(* Logix 5000 project; controller MyControlLogix 1756-L63 rev 15.1; software revision 15.02 *)
// Sample ladder logic for MVI56-AFC module

TASK MainTask (continuous, watchdog 500 ms) : MainProgram

MODULES
   Local : 1756-L63 (ICP 0, rev 15.1)
      AFC : vendor 1 type 0 code 15 (ICP 1, rev 1.1, Output RPI 5 ms)
END_MODULES

TYPE AFC :   // Main user defined data type
STRUCT
   Meters : AFC_Meters[16];   // Stores meter process variables, results, analysis (gas) and module profile
   MeterSignals : AFC_Meter_Reset;   // Sets meter signals (write archive, reset accumulator and select stream)
   ModbusGateway : AFC_Modbus;   // Reads and write data between processor and module modbus table
   ModbusMaster : AFC_ModbusMaster;   // Setup modbus master commands to be sent to remote slaves (through Port 3)
   ModbusPassThru : AFC_ModbusPassThru;   // Modbus pass-thru data
   Prove : AFC_Prove;   // Proving implementation (only firmware 2.07.000 or later)
   Flags : AFC_Flag;   // Wallclock update commands
   EnableMeter : AFC_Meter;   // Enable meters (this action can also be performed through AFC Manager)
   DisableMeter : AFC_Meter;   // Disable meters (this action can also be performed through AFC Manager)
   EnableStatus : AFC_Meter;   // Meter current status (0=disabled, 1=enabled)
   Site_Status : AFC_Site_Status;   // Site status
   Site_Alarms : AFC_Site_Alarms;   // Site Alarms
   CycleCounter : INT;   // Reflects current block ID calculated by ladder to be sent to the module
   inputbuffer : INT[250];   // Input buffer contains the complete block to be copied from the module
   outputbuffer : INT[248];   // Output buffer contains data the complete block to be copied to the module
   clockstructure : AFC_Time;   // Stores clock information
   Util : AFC_Util;   // Convenience variables used by ladder logic
END_STRUCT
END_TYPE

TYPE AFC_Analysis_High :   // High precision (floating point) Gas Analysis support. This feature is only supported for firmware version 2.07.000 or later
STRUCT
   EnableOnce : BOOL;   // Set to ON to request the high precision analysis update one time. It automatically resets to 0 after the request.
   Stream : INT;   // Stream number. Range is 0 (active) and 1 to 4.
   Components : AFC_Components_High;   // AFC High Precision Molar Analysis (floating point)
END_STRUCT
END_TYPE

TYPE AFC_Analysis_Low :   // Low precision (16-bit word) Gas Analysis support.
STRUCT
   EnableContinuous : BOOL;   // Set to ON to update the low precision molar analysis. The data will be updated continuously while the molar analysis is updated.
   Stream : INT;   // Select stream for molar analysis (low precision) update. Valid range is 0 (active) and 1 to 4.
   Components : AFC_Components_Low;   // Gas components in low precision format (16-bit word)
END_STRUCT
END_TYPE

TYPE AFC_Analysis_Status :   // Contains stream configuration information concerning high/low precision.
STRUCT
   Update : BOOL;   // Trigger update of analysis status
   Stream_Precision : SINT[4];   // Stream Precision ( 1 = Low, 2 = High)
   Slot_In_Stream : SINT[4];   // Slot number associated to each stream (0-BASED) Ex: (Slot_In_Stream[0] = 1 means stream 1 is set for slot 2)
   Slot_Precision : SINT[4];   // Precision of each slot (0-BASED) (2=high precision/first slot, 1=low precision,0=high precision/second slot)
END_STRUCT
END_TYPE

TYPE AFC_Components_High :   // High precision gas component analysis (only supported version 2.07.000)
STRUCT
   C1 : REAL;   // Methane
   N2 : REAL;   // Nitrogen
   CO2 : REAL;   // Carbon Dioxide
   C2 : REAL;   // Ethane
   C3 : REAL;   // Propane
   H20 : REAL;   // Water
   H2S : REAL;   // Hydrogen Sulphide
   H2 : REAL;   // Hydrogen
   CO : REAL;   // Carbon Monoxide
   O2 : REAL;   // Oxygen
   IC4 : REAL;   // Iso-butane
   NC4 : REAL;   // Normal Butane
   IC5 : REAL;   // Iso-pentane
   NC5 : REAL;   // Normal-pentane
   C6 : REAL;   // Hexane
   C7 : REAL;   // Heptane
   C8 : REAL;   // Octane
   C9 : REAL;   // Nonane
   C10 : REAL;   // Decane
   He : REAL;   // Helium
   Ar : REAL;   // Argon
   NeoC5 : REAL;   // Not Used
   Ux_User1 : REAL;   // Not Used
   Uy_User2 : REAL;   // Not Used
END_STRUCT
END_TYPE

TYPE AFC_Components_Low :   // Low precision gas component analysis
STRUCT
   C1 : INT;   // Methane
   N2 : INT;   // Nitrogen
   CO2 : INT;   // Carbon dioxide
   C2 : INT;   // Ethane
   C3 : INT;   // Propane
   H20 : INT;   // Water
   H2S : INT;   // Hydrogen sulphide
   H2 : INT;   // Hydrogen
   CO : INT;   // Carbon monoxide
   O2 : INT;   // Oxygen
   IC4 : INT;   // Iso-butane
   NC4 : INT;   // Normal butane
   IC5 : INT;   // Iso-pentane
   NC5 : INT;   // Normal pentane
   C6 : INT;   // Hexane
   C7 : INT;   // Heptane
   C8 : INT;   // Octane
   C9 : INT;   // Nonane
   C10 : INT;   // Decane
   He : INT;   // Helium
   Ar : INT;   // Argon
   NeoC5 : INT;   // Not used
   Ux_User1 : INT;   // Not used
   Uy_User2 : INT;   // Not used
END_STRUCT
END_TYPE

TYPE AFC_Flag :   // Flags contains status information updated by ladder and also trigger bits for clock update
STRUCT
   AFC_Stopped : BOOL;   // Indicates that the module has sent a new input block to be processed by ladder - UPDATED BY LADDER
   AFC_InputSequenceNum : INT;   // Meter number (0 -15) associated to blocks 1-16. Used to update "Profile" (meter type and product group.) UPDATED BY LADDER
   AFC_Set_Clock : BOOL;   // Set to 1 to update module wallclock (using processor as a source) UPDATED BY USER
   plc_set_clock : BOOL;   // Set to 1 to set processor wallclock UPDATED BY USER
END_STRUCT
END_TYPE

TYPE AFC_Meter :   // Used for meter enable and disable tags
STRUCT
   Meter1 : BOOL;   // Meter 1
   Meter2 : BOOL;   // Meter 2
   Meter3 : BOOL;   // Meter 3
   Meter4 : BOOL;   // Meter 4
   Meter5 : BOOL;   // Meter 5
   Meter6 : BOOL;   // Meter 6
   Meter7 : BOOL;   // Meter 7
   Meter8 : BOOL;   // Meter 8
   Meter9 : BOOL;   // Meter 9
   Meter10 : BOOL;   // Meter 10
   Meter11 : BOOL;   // Meter 11
   Meter12 : BOOL;   // Meter 12
   Meter13 : BOOL;   // Meter 13
   Meter14 : BOOL;   // Meter 14
   Meter15 : BOOL;   // Meter 15
   Meter16 : BOOL;   // Meter 16
END_STRUCT
END_TYPE

TYPE AFC_Meter_Analysis :   // Meter analysis components. Allows the processor to update molar analysis for low precision and high precision streams.
STRUCT
   Low_Precision : AFC_Analysis_Low;   // Low precision gas components (16-bit word per component)
   High_Precision : AFC_Analysis_High;   // High precision gas components (floating point per component). Only supported for firmware version 2.07.000 or later
   Status : AFC_Analysis_Status;   // Stream analysis status - contains stream and slot configuration data
END_STRUCT
END_TYPE

TYPE AFC_Meter_Differential_Gas_Input :   // Calculation results for differential meter with gas product
STRUCT
   Net_Accumulator : DINT;   // Net accumulator
   Net_Flowrate : REAL;   // Net flow rate
   Gross_Flowrate : REAL;   // Gross flow rate
   Fpv : REAL;   // Super compressibility
   Cprime : REAL;   // Cprime
END_STRUCT
END_TYPE

TYPE AFC_Meter_Differential_Gas_Output :   // Process Variables for differential meter with gas product
STRUCT
   Temperature : REAL;   // Temperature
   Pressure : REAL;   // Static pressure
   Differential_Pressure : REAL;   // Differential pressure if Primary Input = Differential pressure OR Flow Rate if Primary Input = Flow rate
END_STRUCT
END_TYPE

TYPE AFC_Meter_Differential_Liquid_Input :   // Calculation Results for differential meter with lliquid product
STRUCT
   Net_Accumulator : DINT;   // Net accumulator
   Net_Flowrate : REAL;   // Net flow rate
   Gross_Accumulator : DINT;   // Gross acumulator
   Gross_Standard_Accumulator : DINT;   // Gross standard accumulator
   Mass_Accumulator : DINT;   // Mass accumulator
END_STRUCT
END_TYPE

TYPE AFC_Meter_Differential_Liquid_Output :   // Process Variables for differential meter with liquid product
STRUCT
   Water_Percent : INT;   // Water %
   Temperature : REAL;   // Temperature
   Pressure : REAL;   // Static Pressure
   Differential_Pressure : REAL;   // Differential pressure if Primary Input = Differential pressure OR Flow Rate if Primary Input = Flow rate
   Density : REAL;   // Density
END_STRUCT
END_TYPE

TYPE AFC_Meter_Linear_Gas_Input :   // Calculation Results for linear meter with gas product
STRUCT
   Net_Accumulator : DINT;   // Net accumulator
   Net_Flowrate : REAL;   // Net flow rate
   Gross_Flowrate : REAL;   // Gross flow rate
   Fpv : REAL;   // Supercompressibility
   CPrime : REAL;   // CPrime
END_STRUCT
END_TYPE

TYPE AFC_Meter_Linear_Gas_Output :   // Process Variables for linear meter with gas product
STRUCT
   Temperature : REAL;   // Temperature
   Pressure : REAL;   // Pressure
   Meter_Pulses : DINT;   // Pulse count
   Pulse_Frequency : REAL;   // Pulse Frequency (Hz)
END_STRUCT
END_TYPE

TYPE AFC_Meter_Linear_Liquid_Input :   // Calculation Results for linear meter with liquid product
STRUCT
   Net_Accumulator : DINT;   // Net accumulator
   Net_Flowrate : REAL;   // Net flow rate
   Gross_Accumulator : DINT;   // Gross accumulator
   Gross_Standard_Accumulator : DINT;   // Gross standard accumulator
   Mass_Accumulator : DINT;   // Mass accumulator
END_STRUCT
END_TYPE

TYPE AFC_Meter_Linear_Liquid_Output :   // Process Variables for linear meter with liquid product
STRUCT
   Water_Percent : INT;   // Water (%)
   Temperature : REAL;   // Temperature
   Pressure : REAL;   // Pressure
   Meter_Pulses : DINT;   // Meter pulses
   Density : REAL;   // Density
   Pulse_Frequency : REAL;   // Pulse frequency (Hz)
END_STRUCT
END_TYPE

TYPE AFC_Meter_Reset :   // Meter signals to request for reset accumulator, select stream and write archives.
STRUCT
   Enable : BOOL;   // Enable meter signal request. UPDATED BY USER
   BID : INT;   // Block ID for meter signal request. UPDATED BY LOGIC
   Meter : INT;   // Meter number (1-16) associated to signal request UPDATED BY USER
   Action : INT;   // Action word built from Signal bits (UPDATED by USER)
   Signals : AFC_Meter_Signals;   // Signals request bits
   ResetOnce : BOOL;   // Request signal update once
   LastBlockID : INT;   // Last block ID associated to signals request
END_STRUCT
END_TYPE

TYPE AFC_Meter_Results :   // AFC meter results calculated by the module to the processor
STRUCT
   BID : INT;   // Block ID associated to calculation results
   Alarms : INT;   // Meter alarms
   DifferentialGas : AFC_Meter_Differential_Gas_Input;   // Differential meter / product gas
   DifferentialLiquid : AFC_Meter_Differential_Liquid_Input;   // Differential meter / product liquid
   LinearGas : AFC_Meter_Linear_Gas_Input;   // Linear meter / product gas
   LinearLiquid : AFC_Meter_Linear_Liquid_Input;   // Linear meter / product liquid
END_STRUCT
END_TYPE

TYPE AFC_Meter_Signals :   // Meter signals options
STRUCT
   Sel_Stream1 : BOOL;   // Set to 1 to select stream 1
   Sel_Stream2 : BOOL;   // Set to 1 to select stream 2
   Sel_Stream3 : BOOL;   // Set to 1 to select stream 3
   Sel_Stream4 : BOOL;   // Set to 1 to select stream 4
   Res_Acc1 : BOOL;   // Set to 1 to reset resettable accumulator 1
   Res_Acc2 : BOOL;   // Set to 1 to reset resettable accumulator 2
   Res_Acc3 : BOOL;   // Set to 1 to reset resettable accumulator 3
   Res_Acc4 : BOOL;   // Set to 1 to reset resettable accumulator 4
   Wr_Daily_Archive : BOOL;   // Set to 1 to write daily archive
   Wr_Hrly_Archive : BOOL;   // Set to 1 to write hourly archive
END_STRUCT
END_TYPE

TYPE AFC_Meter_Variables :   // Meter process variables from processor to the module.
STRUCT
   BID : INT;   // Block ID associated to meter process variable block (from processor to the module)
   DifferentialGas : AFC_Meter_Differential_Gas_Output;   // Differential meter and gas product
   DifferentialLiquid : AFC_Meter_Differential_Liquid_Output;   // Differential meter and liquid product
   LinearGas : AFC_Meter_Linear_Gas_Output;   // Linear meter and gas product
   LinearLiquid : AFC_Meter_Linear_Liquid_Output;   // Linear meter and liquid product
END_STRUCT
END_TYPE

TYPE AFC_Meters :   // Main meter data structure. Contains process variables, calculation results, gas analysis, profile update
STRUCT
   Variables : AFC_Meter_Variables;   // Input process variables to be transferred to the module
   Results : AFC_Meter_Results;   // Calculation results transferred from the module
   Analysis : AFC_Meter_Analysis;   // Molar Analysis data to be transferred to the module (only for gas products with online gas chromatograph applications)
   Profile : AFC_Status;   // Module profile (meter type/product group) transfered from the module
END_STRUCT
END_TYPE

TYPE AFC_Modbus :   // Modbus Gateway data structure. Select the number of commands to be used (1 to 10). O will disable this funcionality.
STRUCT
   CommandCount : INT;   // Defines the number of Modbus Gateway Blocks to be used (1 to 10). Set to 0 to disable the feature.
   Command : AFC_ModbusGateway[10];   // Modbus gateway commands - contains setup and modbus data
END_STRUCT
END_TYPE

TYPE AFC_ModbusConfig :   // Modbus gateway configuration options
STRUCT
   Enable : BOOL;   // Set to 1 to enable modbus gateway command (0=disable)
   StartRegister : INT;   // Start modbus address
   RegisterCount : INT;   // Word count (200 max)
   FunctionType_Write : BOOL;   // 0 = read command, 1 = write command
   RegisterType_Input : BOOL;   // 0 = holding register, 1 = input register
   SlaveType_Virtual : BOOL;   // 0 = primary slave, 1 = virtual slave
END_STRUCT
END_TYPE

TYPE AFC_ModbusGateway :   // Modbus gateway complete data structure
STRUCT
   Config : AFC_ModbusConfig;   // Config data to be entered by the user.
   BOD : INT;   // Block ID automatically generated by ladder
   WriteData : INT[200];   // Contains modbus data written to the module (write commands)
   BID : INT;   // Block ID automatically generated by ladder
   ReadData : INT[200];   // Contains modbus data read from the module (read commands)
END_STRUCT
END_TYPE

TYPE AFC_ModbusMaster :   // Modbus master operation. Port 3 must be configured as modbus master through AFC Manager to use this feature.
STRUCT
   Enable : BOOL;   // Enable the modbus master functionality
   CommandIndex : INT;   // Selects which command index will be executed
   Command : AFC_ModbusMasterElement[10];   // Each command contains a specific modbus request to be sent out of the port
END_STRUCT
END_TYPE

TYPE AFC_ModbusMasterConfig :   // Modbus master command settings
STRUCT
   Enable : BOOL;   // Set to 1 to enable command (0=disable)
   FunctionType_Write : BOOL;   // Set to 1 to select write command (0=read command)
   RegisterBank_Input : BOOL;   // Set to 1 to select input register (0=holding register)
   DataType : AFC_ModbusMasterDataType;   // Select data type format
   SwapOption : AFC_ModbusMasterSwap;   // Select byte and word swap (1 = swap, 0 = no swap)
   Type_Swap : INT;   // This value is calculated by ladder logic and must not be modified by user
   SlaveAddress : INT;   // Modbus slave address of remote device
   ModbusAddress : INT;   // Modbus data address on remote slave
   ElementCount : INT;   // Number of data elements (125 words)
END_STRUCT
END_TYPE

TYPE AFC_ModbusMasterDataType :   // Modbus master data type selection
STRUCT
   Bit : BOOL;   // bit type
   Word : BOOL;   // word type (16-bit)
   Long : BOOL;   // long integer (32-bit)
   LongRemote : BOOL;   // long integer (32-bit)
END_STRUCT
END_TYPE

TYPE AFC_ModbusMasterElement :   // odbus master controller tag. Requires port 3 to be configured as a modbus master device.
STRUCT
   Output : AFC_ModbusMasterOut;   // From processor to the module
   Input : AFC_ModbusMasterIn;   // From module to the processor
END_STRUCT
END_TYPE

TYPE AFC_ModbusMasterIn :   // Modbus master input tag.
STRUCT
   BID : INT;   // Block id associated to modbus master request
   TransactionNumber : INT;   // Transaction number associated to modbus command index
   ErrorCode : INT;   // Error code associated to modbus master command
   Pending : BOOL;   // Pending modbus master command - waiting for modbus response
   ReadData : INT[100];   // Data read fro mremote slave device
END_STRUCT
END_TYPE

TYPE AFC_ModbusMasterOut :   // Modbus master request from processor to the module
STRUCT
   Config : AFC_ModbusMasterConfig;   // Modbus master command configuration settings
   TransactionNumber : INT;   // Transaction number used to keep track of diffeernt commands (echoed back in response)
   BOD : INT;   // Block output ID
   WriteData : INT[100];   // Write data associated to the write command
END_STRUCT
END_TYPE

TYPE AFC_ModbusMasterSwap :   // Modbus master swap words/ swap bytes
STRUCT
   Swap_Words : BOOL;   // Swap words
   Swap_Bytes : BOOL;   // Swap bytes
END_STRUCT
END_TYPE

TYPE AFC_ModbusPassThru :   // AFC modbus pass through controller tag
STRUCT
   Output : AFC_ModbusPassThruOut;   // Values to be transferred from processor to the module
   Input : AFC_ModbusPassThruIn;   // Values to be transferred from module to processor
END_STRUCT
END_TYPE

TYPE AFC_ModbusPassThruIn :   // Modbus pass through input
STRUCT
   BID : INT;   // Calculated by ladder logic
   MessagePresent : BOOL;   // Message present in the response block
   Function_BitWrite : BOOL;   // Function bit write
   OverflowError : BOOL;   // Overflow error flag
   ModbusAddress : INT;   // Destination modbus address
   RegisterCount : INT;   // Number of elements associated to command
   ReadData_Word : INT[125];   // Contains received data for word commands
   ReadData_Bit : BOOL[2016];   // Contains received data for bit commands
END_STRUCT
END_TYPE

TYPE AFC_ModbusPassThruOut :   // AFC Modbus pass through output block fro mprocessor to the module
STRUCT
   BOD : INT;   // Automatically calculated by sample ladder
   Enable : BOOL;   // Set to 1 to enable pass-thru funcionality (requires AFC Manager setting)
END_STRUCT
END_TYPE

TYPE AFC_Prove :   // Implements prove funcionality. Supported only for firmware version 2.07 or later.
STRUCT
   Output : AFC_Prove_Output;   // Prover output block to the module
   Input : AFC_Prove_Input;   // Prover input block from the module
END_STRUCT
END_TYPE

TYPE AFC_Prove_Config :   // Controlls (configuration settings) associated to the prover
STRUCT
   Enable : AFC_Prove_Config_Enable;   // Controls at enable
   Accept : AFC_Prove_Config_Accept;   // Controls at accept
END_STRUCT
END_TYPE

TYPE AFC_Prove_Config_Accept :   // Prove controls at accept. If auto-accept is selected must be available at enable
STRUCT
   Requested_Interpolation_Point : INT;   // requested interpolation point (0 nearest)
   Apply_MF_Change_All_Streams : BOOL;   // Apply change in meter factor to all streams
   Apply_MF_Change_Curve : BOOL;   // Apply change in meter factor to all curve points
   Apply_New_MF : BOOL;   // CApply new meter factor
END_STRUCT
END_TYPE

TYPE AFC_Prove_Config_Enable :   // Prove controls at enable
STRUCT
   Meter_Number : INT;   // Meter number requested (1-16)
   Auto_Accept_Prove : BOOL;   // Auto-accept the prove
   Auto_Continue_Prove : BOOL;   // Auto-continue the prove
END_STRUCT
END_TYPE

TYPE AFC_Prove_Input :   // AFC Prove input block
STRUCT
   Config : AFC_Prove_Input_Config;   // AFC prover input configuration
   Status : AFC_Prove_Status;   // AFC prover status
   Error_Code : INT;   // Prove error code
   Prove_controls_Echo : INT;   // AFC module Echos the state of the Prove Controls
   Requested_Meter_Echo : INT;   // AFC module Echos the Meter number requested
   Requested_Curve_Point_Echo : INT;   // AFC module Echos the requested Curve Point
   Run_Results : AFC_Prove_Run_Results;   // Prove and run results
   Prove_Enabled : BOOL;   // ON if prove is enabled. This flag is coped from inputbuffer[247]
END_STRUCT
END_TYPE

TYPE AFC_Prove_Input_Config :   // Prove input block results - prover configuration
STRUCT
   Type : INT;   // Prover type
   Options : INT;   // Prover options
   Runs_Per_Prove_Total : INT;   // Total runs per prove
   Runs_Per_Prove_Selected : INT;   // Selected runs per prove
   Max_Runs_before_Abort : INT;   // Max total runs before abort
   Short_Passes_Per_Run : INT;   // Short passes per run if bidir = 2 , else 0
END_STRUCT
END_TYPE

TYPE AFC_Prove_Output :   // AFC Prove output block
STRUCT
   Process : AFC_Prove_Process;   // Process Variables
   Signals : AFC_Prove_Signals;   // AFC Prove Signals (triggers the proving update)
   Config : AFC_Prove_Config;   // AFC Prove Control (configuration settings)
   Pulse_Counts : AFC_Prove_Pulse_Count;   // Pulse counts to be updated at the end of the run/pass
END_STRUCT
END_TYPE

TYPE AFC_Prove_Phase_Bitmap :   // AFC prove phase bitmap
STRUCT
   Not_Selected : BOOL;   // Not selected
   Active : BOOL;   // Active, not counting
   Counting_Past_1st_Switch : BOOL;   // Counting past 1st switch for Udir and forward leg for Bdir)
   Past_2nd_Switch_Fwd_Leg : BOOL;   // Past 2nd switch forward leg (bidirectional only)
   Past_1st_Swith_Ret_Leg : BOOL;   // Past 1st switch return leg (bidirectional only)
   Run_Complete : BOOL;   // Run complete. past 2nd switch.
END_STRUCT
END_TYPE

TYPE AFC_Prove_Process :   // Prove process output from processor to the module
STRUCT
   Sequencing : AFC_Prove_Sequencing;   // Prover sequencing
   Temperature : REAL;   // Temperature for Single Probe provers. And Inlet Temperature for Dual Probe Provers.
   Outlet_Temperature : REAL;   // Outlet Temperature for Provers with Dual Probes.
   Switch_Bar_Temperature : REAL;   // Switch bar temperature
   Pressure : REAL;   // Pressure for Single Probe provers. And Inlet Pressure for Dual Probe Provers.
   Outlet_Pressure : REAL;   // Outlet Pressure for Provers with Dual Probes.
   Prover_Density : REAL;   // Prover density
END_STRUCT
END_TYPE

TYPE AFC_Prove_Pulse_Count :   // Values to be supplied at the end of the pass/run
STRUCT
   Meter : DINT;   // Meter pulse count
   Master_Meter : DINT;   // Master meter pulse count
END_STRUCT
END_TYPE

TYPE AFC_Prove_Run_Results :   // Run results of the prove. Copied from the module to the pocessor
STRUCT
   Count_Attempted : INT;   // Run count attempted
   Count_Completed : INT;   // Run count completed
   Count_Selected : INT;   // Run count selected
   Runs_Selected : INT;   // Bit Mapped Runs selected for calculations from completed runs
   New_Meter_Factor : REAL;   // New meter factor
   Change_In_Meter_Factor : REAL;   // Change in meter factor
END_STRUCT
END_TYPE

TYPE AFC_Prove_Sequencing :   // AFC prove sequencing tag for phase selection and ball positioning
STRUCT
   Phase : AFC_Prove_Phase_Bitmap;   // AFC phase sequencing
   Ball_Position_Ready : BOOL;   // Ball position: Ready (Udir & Bdir only; fwd leg Bdir)
   Ball_Position_Sealed : BOOL;   // Ball position: Sealed (Udir & Bdir only; fwd leg Bdir)
   Ball_Position_Ready_Bwd_Leg : BOOL;   // Ball position: Ready bwd leg (Bdir only)
   Ball_Position_Sealed_Bwd_Leg : BOOL;   // Ball position: Sealed bwd leg (Bdir only)
END_STRUCT
END_TYPE

TYPE AFC_Prove_Signals :   // Contains the proving signals that will trigger specific tasks from the module
STRUCT
   EnableProve : BOOL;   // Enables the prove
   AcceptProve : BOOL;   // Accepts the prove
   RejectProve : BOOL;   // Reject the prove
   RunStart : BOOL;   // Starts the run
   RunComplete : BOOL;   // Flags that the run is complete
   RunCancel : BOOL;   // Cancels the run
   RunDelete : BOOL;   // Deletes the run
   PassComplete : BOOL;   // Flag that the pass is complete
   PauseProve : BOOL;   // Pauses the Proving Process
   AbortProve : BOOL;   // Aborts the prove
END_STRUCT
END_TYPE

TYPE AFC_Prove_Status :   // Status of the prove (returned from the module to the processor)
STRUCT
   Prove_Accepted : BOOL;   // Prove was accepted
   Meter_Factor_Applied : BOOL;   // Meter factor was applied
   MF_Applied_To_Curve : BOOL;   // Meter factor was applied to all points in the curve
   MF_Applied_To_Streams : BOOL;   // Meter factor was applied to all streams
   Prove_Rejected_By_Command : BOOL;   // Prove was rejected by command
   Prove_Rejected_No_Runs : BOOL;   // Prove was rejected - empty prove (no runs)
   Prove_Rejected_Divide_By_0 : BOOL;   // Prove was rejected - divide by 0
   Prove_Enabled : BOOL;   // Prove is enabled
   Proving_Run_In_Progress : BOOL;   // Proving run is in progress
   Prove_Rejected_Abort : BOOL;   // Prove rejected: abort
   Prove_Paused : BOOL;   // Prove is paused
   Run_Cancelled : BOOL;   // Run Is cancelled
   Run_Timed_Out : BOOL;   // Run timed out
END_STRUCT
END_TYPE

TYPE AFC_Site_Alarms :   // Indicates if a meter has any alarms
STRUCT
   Meter1 : BOOL;   // Meter in alarm
   Meter2 : BOOL;   // Meter in alarm
   Meter3 : BOOL;   // Meter in alarm
   Meter4 : BOOL;   // Meter in alarm
   Meter5 : BOOL;   // Meter in alarm
   Meter6 : BOOL;   // Meter in alarm
   Meter7 : BOOL;   // Meter in alarm
   Meter8 : BOOL;   // Meter in alarm
   Meter9 : BOOL;   // Meter in alarm
   Meter10 : BOOL;   // Meter in alarm
   Meter11 : BOOL;   // Meter in alarm
   Meter12 : BOOL;   // Meter in alarm
   Meter13 : BOOL;   // Meter in alarm
   Meter14 : BOOL;   // Meter in alarm
   Meter15 : BOOL;   // Meter in alarm
   Meter16 : BOOL;   // Meter in alarm
END_STRUCT
END_TYPE

TYPE AFC_Site_Status :   // Site status bits - contains general information about the module - not meter specific
STRUCT
   AFC_ACTIVE : BOOL;   // AFC active
   Checksum_Alarms : BOOL;   // Checkum alarm active
   reserved2 : BOOL;
   reserved3 : BOOL;
   PLC_HALTED : BOOL;   // PLC in program mode or missing
   Cfg_changed : BOOL;   // Configuration changed
   Powerup : BOOL;   // Module powered up
   ColdStart : BOOL;   // Module performed cold start (BBRAM initialized)
   HardPassword : BOOL;   // Hard password selected
   reserved9 : BOOL;
   reserved10 : BOOL;
   reserved11 : BOOL;
   reserved12 : BOOL;
   reserved13 : BOOL;
   reserved14 : BOOL;
   reserved15 : BOOL;
END_STRUCT
END_TYPE

TYPE AFC_Status :   // General meter configuration profile
STRUCT
   MeterType : BOOL;   // 0=Differential, 1=Linear
   ProductGroup : BOOL;   // 0=Gas, 1=Liquid
   SelectedStream : INT;   // Selected Stream (1 through 4). Only supported for firmware version 2.05.000 or later
END_STRUCT
END_TYPE

TYPE AFC_Time :   // AFC time format used for walclock update
STRUCT
   Year : DINT;   // Year
   Month : DINT;   // Month
   Day : DINT;   // Day
   Hour : DINT;   // Hour
   Minute : DINT;   // Minute
   second : DINT;   // Seconds
   msec : DINT;   // Milliseconds
END_STRUCT
END_TYPE

TYPE AFC_Util :   // Used for internal ladder logic usage. These values must not be changed by user application.
STRUCT
   MeterIndex1 : INT;   // Meter index for process variable calculation
   Offset1 : INT;   // Offset for meter process calculation
   MeterIndex2 : INT;   // Meter index for calculation results
   Offset2 : INT;   // Offset for calculation results
   SignalsTimer : TIMER;   // Signals timer
   IndexOut : INT;   // Index output
   IndexIn : INT;   // Index input
   CycleCounterRollover : INT;   // Rollover value for cycle counter for block ID calculation
   LongCount : INT;   // Long count for modbus master command
   LastRegularBlockID : INT;   // Rollover block ID
   Current_meter : SINT;   // Current meter number analysis update
   MaskedStream : INT;   // Masked stream
   AnalysisMeterNumber : INT;   // Analysis meter number
   AnalysisBID : INT;   // Analysis block ID
   AnalysisStreamMasked : INT;   // Analysis stream masked information
   v206orLater : INT;   // indicates if the meter is 2.06 or later so the module supports high precision analysis
   AnalysisHighPrecisionBOD : INT;   // Analysis high precision number
   Firmware_Version : SINT[2];   // Firmware version number
   Firmware_Revision : INT;   // firmware revision number
   AnalysisHMeter : INT;   // Meter associated to molar high precision
   SlotPrecision : SINT[4];   // Slot precision number for stream precision calculation
   SlotInStream : DINT[4];   // Slot number for stream X
   PowerUp_HighAnalysis : BOOL;   // Request high analysis block upon power up
   Meter_HighAnalysis : INT;   // Meter number for high precision analysis
   TempSlotInStream : SINT;   // Used to calculate stream precision based on slot precision
   AnalysisHighPrecisionBID : INT[16];   // High precision block ID
   AnalysisHighPrecisionBID_Update : INT;   // molar block id update
   Reinitialize_Timer : TIMER;   // Timer to initialize block ID if freezes
   Prover_Phase : INT;   // Prover phase integer word to assemble all bits
   Prover_Signals : INT;   // Prover signals integer word to assemble all bits
   Prover_Controls : INT;   // Prover control word to assemble all bits
END_STRUCT
END_TYPE

VAR_GLOBAL   (* controller tags *)
   AFC56 : AFC;
        .PROVE.OUTPUT.SIGNALS.ABORTPROVE   // Same effect as AFC Manager performing configuration changes while in the Proving process.
        .PROVE.INPUT.RUN_RESULTS.RUNS_SELECTED.0   // 1 run selected
        .PROVE.INPUT.RUN_RESULTS.RUNS_SELECTED.1   // 2 runs selected
        .PROVE.INPUT.RUN_RESULTS.RUNS_SELECTED.2   // 3 runs selected
        .PROVE.INPUT.RUN_RESULTS.RUNS_SELECTED.3   // 4 runs selected
        .PROVE.INPUT.RUN_RESULTS.RUNS_SELECTED.4   // 5 runs selected
        .PROVE.INPUT.RUN_RESULTS.RUNS_SELECTED.5   // 6 runs selected
        .PROVE.INPUT.RUN_RESULTS.RUNS_SELECTED.6   // 7 runs selected
        .PROVE.INPUT.RUN_RESULTS.RUNS_SELECTED.7   // 8 runs selected
        .UTIL.PROVER_SIGNALS.0   // Reset error
        .UTIL.PROVER_SIGNALS.1   // Enable prove
        .UTIL.PROVER_SIGNALS.2   // Accept prove
        .UTIL.PROVER_SIGNALS.3   // Reject prove
        .UTIL.PROVER_SIGNALS.4   // Run start
        .UTIL.PROVER_SIGNALS.5   // Run complete
        .UTIL.PROVER_SIGNALS.6   // Run cancel
        .UTIL.PROVER_SIGNALS.7   // Run delete
        .UTIL.PROVER_SIGNALS.9   // Pass complete
        .UTIL.PROVER_SIGNALS.12   // Pause prove
        .UTIL.PROVER_SIGNALS.13   // Select runs
        .UTIL.PROVER_SIGNALS.14   // Abort prove
END_VAR

PROGRAM MainProgram   (* main routine MainRoutine *)

ROUTINE AFC   (* ladder *)
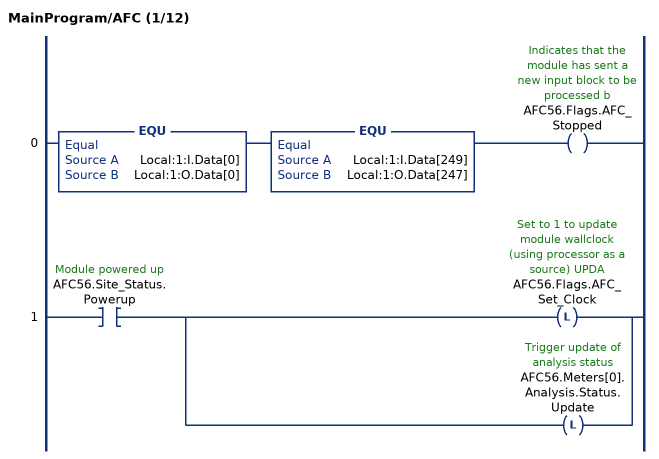
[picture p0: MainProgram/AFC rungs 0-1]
   0: EQU(Local:1:I.Data[0],Local:1:O.Data[0])EQU(Local:1:I.Data[249],Local:1:O.Data[247])OTE(AFC56.Flags.AFC_Stopped);
   1: XIC(AFC56.Site_Status.Powerup)[OTL(AFC56.Flags.AFC_Set_Clock) ,OTL(AFC56.Meters[0].Analysis.Status.Update) ];
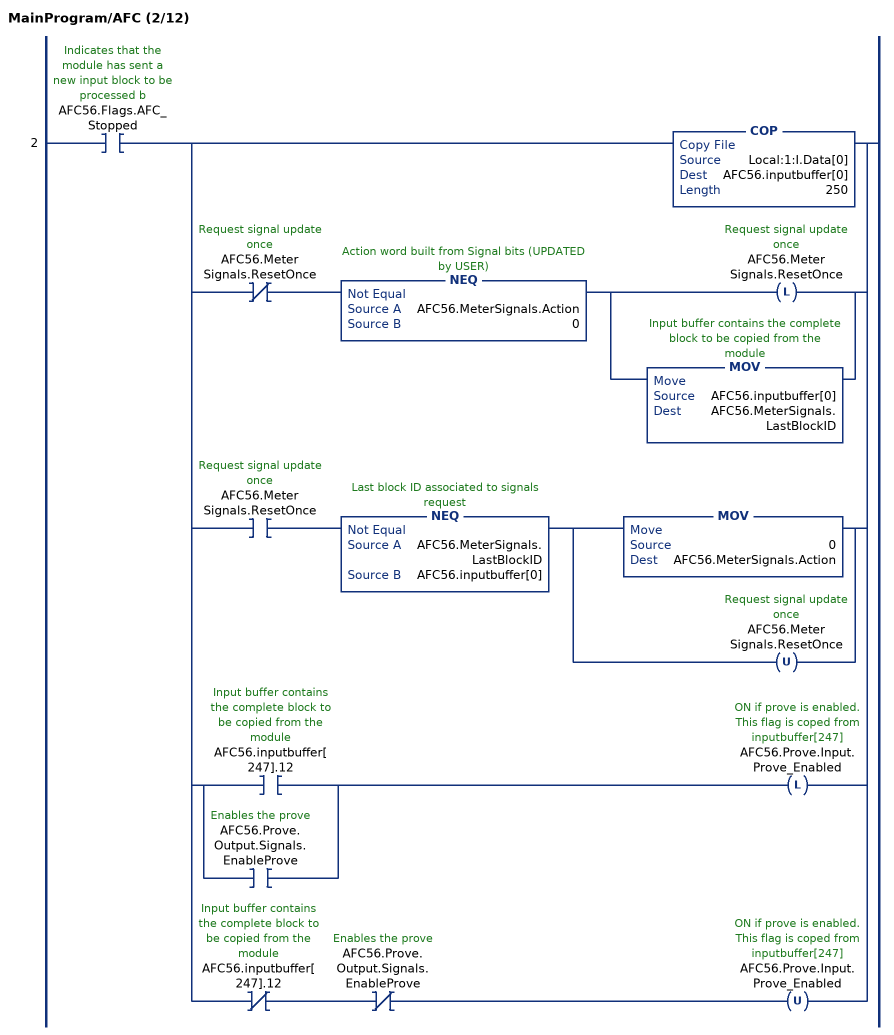
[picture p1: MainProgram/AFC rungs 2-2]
   2: XIC(AFC56.Flags.AFC_Stopped)[COP(Local:1:I.Data[0],AFC56.inputbuffer[0],250) ,XIO(AFC56.MeterSignals.ResetOnce) NEQ(AFC56.MeterSignals.Action,0) [OTL(AFC56.MeterSignals.ResetOnce) ,MOV(AFC56.inputbuffer[0],AFC56.MeterSignals.LastBlockID) ] ,XIC(AFC56.MeterSignals.ResetOnce) NEQ(AFC56.MeterSignals.LastBlockID,AFC56.inputbuffer[0]) [MOV(0,AFC56.MeterSignals.Action) ,OTU(AFC56.MeterSignals.ResetOnce) ] ,[XIC(AFC56.inputbuffer[247].12) ,XIC(AFC56.Prove.Output.Signals.EnableProve) ] OTL(AFC56.Prove.Input.Prove_Enabled) ,XIO(AFC56.inputbuffer[247].12) XIO(AFC56.Prove.Output.Signals.EnableProve) OTU(AFC56.Prove.Input.Prove_Enabled) ];
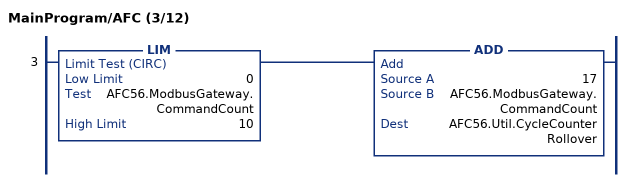
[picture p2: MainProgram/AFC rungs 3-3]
   3: LIM(0,AFC56.ModbusGateway.CommandCount,10)ADD(17,AFC56.ModbusGateway.CommandCount,AFC56.Util.CycleCounterRollover);
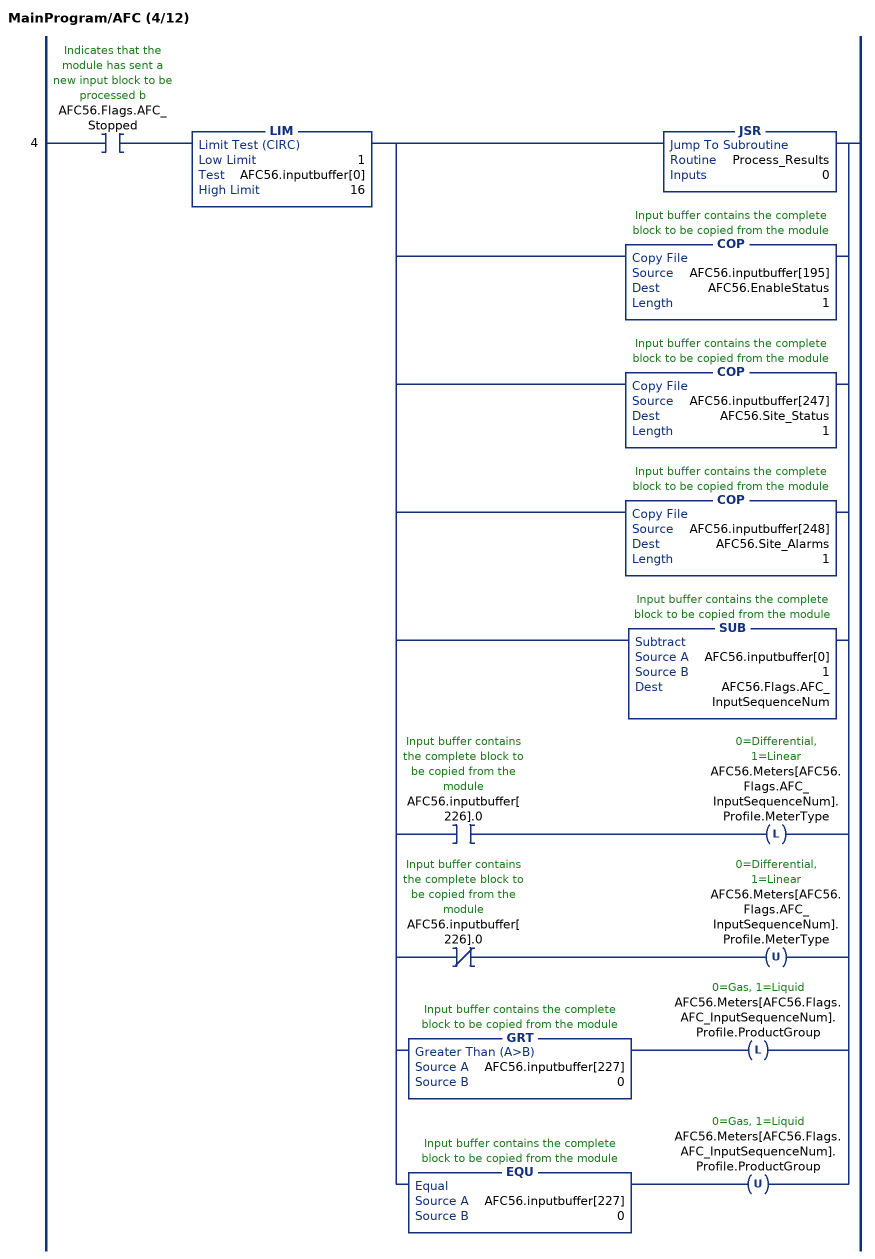
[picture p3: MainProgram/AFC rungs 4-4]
   4: XIC(AFC56.Flags.AFC_Stopped)LIM(1,AFC56.inputbuffer[0],16)[JSR(Process_Results,0) ,COP(AFC56.inputbuffer[195],AFC56.EnableStatus,1) ,COP(AFC56.inputbuffer[247],AFC56.Site_Status,1) ,COP(AFC56.inputbuffer[248],AFC56.Site_Alarms,1) ,SUB(AFC56.inputbuffer[0],1,AFC56.Flags.AFC_InputSequenceNum) ,XIC(AFC56.inputbuffer[226].0) OTL(AFC56.Meters[AFC56.Flags.AFC_InputSequenceNum].Profile.MeterType) ,XIO(AFC56.inputbuffer[226].0) OTU(AFC56.Meters[AFC56.Flags.AFC_InputSequenceNum].Profile.MeterType) ,GRT(AFC56.inputbuffer[227],0) OTL(AFC56.Meters[AFC56.Flags.AFC_InputSequenceNum].Profile.ProductGroup) ,EQU(AFC56.inputbuffer[227],0) OTU(AFC56.Meters[AFC56.Flags.AFC_InputSequenceNum].Profile.ProductGroup) ];
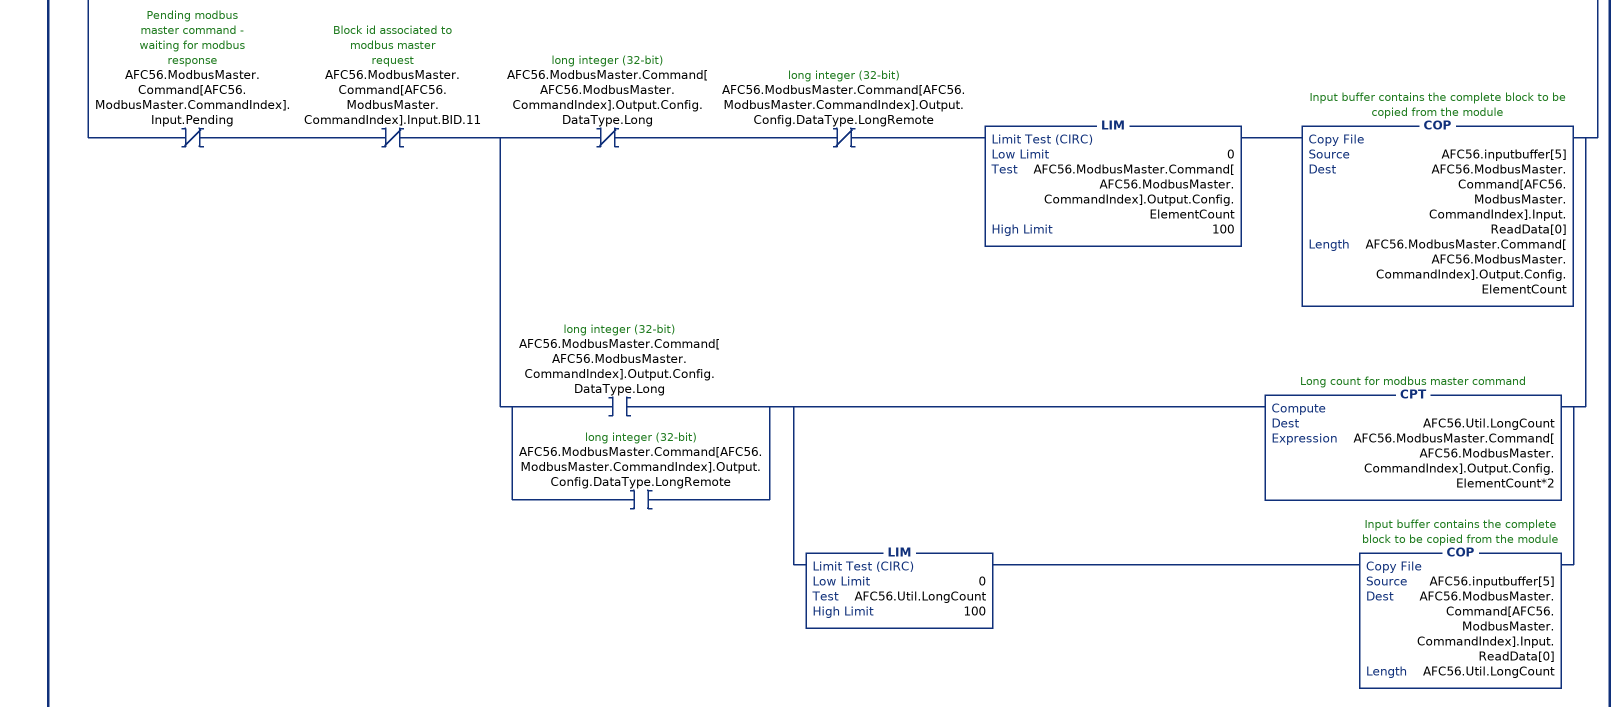
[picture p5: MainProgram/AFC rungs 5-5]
   5: XIC(AFC56.Flags.AFC_Stopped)[EQU(AFC56.inputbuffer[0],1000) ,EQU(AFC56.inputbuffer[0],1001) ]XIC(AFC56.ModbusMaster.Enable)EQU(AFC56.inputbuffer[3],AFC56.ModbusMaster.Command[AFC56.ModbusMaster.CommandIndex].Output.TransactionNumber)[MOV(AFC56.inputbuffer[2],AFC56.ModbusMaster.Command[AFC56.ModbusMaster.CommandIndex].Input.BID) ,XIC(AFC56.ModbusMaster.Command[AFC56.ModbusMaster.CommandIndex].Input.BID.0) OTE(AFC56.ModbusMaster.Command[AFC56.ModbusMaster.CommandIndex].Input.Pending) ,MOV(AFC56.inputbuffer[3],AFC56.ModbusMaster.Command[AFC56.ModbusMaster.CommandIndex].Input.TransactionNumber) ,MOV(AFC56.inputbuffer[4],AFC56.ModbusMaster.Command[AFC56.ModbusMaster.CommandIndex].Input.ErrorCode) ,XIO(AFC56.ModbusMaster.Command[AFC56.ModbusMaster.CommandIndex].Input.Pending) XIO(AFC56.ModbusMaster.Command[AFC56.ModbusMaster.CommandIndex].Input.BID.11) [XIO(AFC56.ModbusMaster.Command[AFC56.ModbusMaster.CommandIndex].Output.Config.DataType.Long) XIO(AFC56.ModbusMaster.Command[AFC56.ModbusMaster.CommandIndex].Output.Config.DataType.LongRemote) LIM(0,AFC56.ModbusMaster.Command[AFC56.ModbusMaster.CommandIndex].Output.Config.ElementCount,100) COP(AFC56.inputbuffer[5],AFC56.ModbusMaster.Command[AFC56.ModbusMaster.CommandIndex].Input.ReadData[0],AFC56.ModbusMaster.Command[AFC56.ModbusMaster.CommandIndex].Output.Config.ElementCount) ,[XIC(AFC56.ModbusMaster.Command[AFC56.ModbusMaster.CommandIndex].Output.Config.DataType.Long) ,XIC(AFC56.ModbusMaster.Command[AFC56.ModbusMaster.CommandIndex].Output.Config.DataType.LongRemote) ] [CPT(AFC56.Util.LongCount,AFC56.ModbusMaster.Command[AFC56.ModbusMaster.CommandIndex].Output.Config.ElementCount*2) ,LIM(0,AFC56.Util.LongCount,100) COP(AFC56.inputbuffer[5],AFC56.ModbusMaster.Command[AFC56.ModbusMaster.CommandIndex].Input.ReadData[0],AFC56.Util.LongCount) ] ] ];
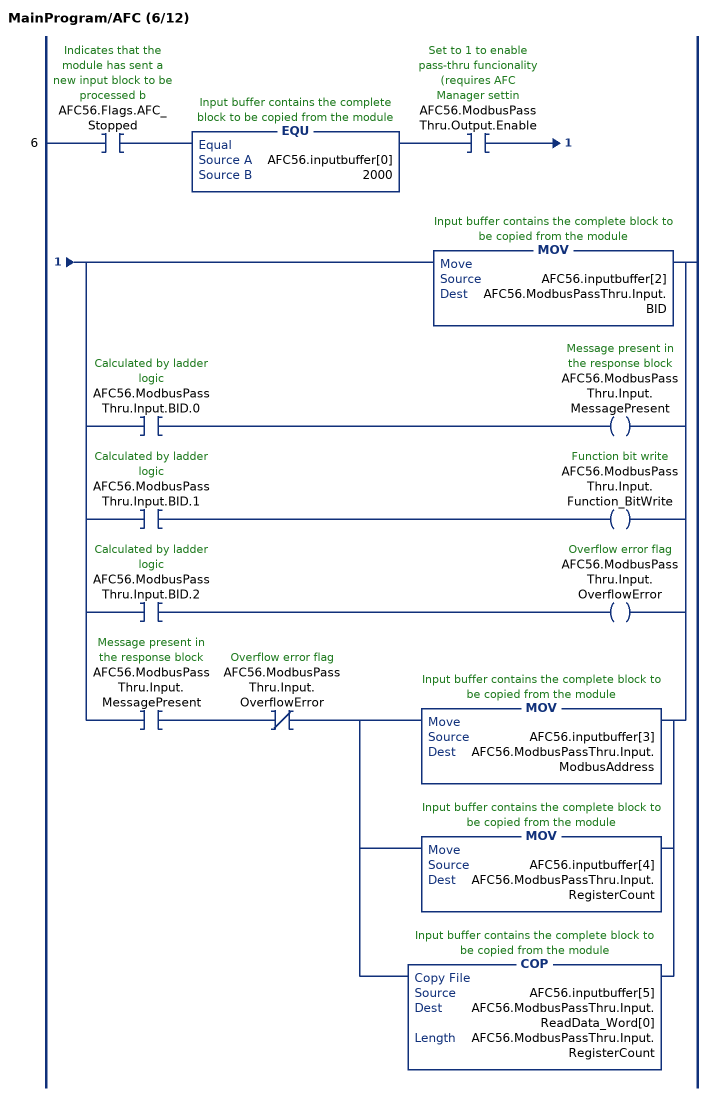
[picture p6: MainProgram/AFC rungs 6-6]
   6: XIC(AFC56.Flags.AFC_Stopped)EQU(AFC56.inputbuffer[0],2000)XIC(AFC56.ModbusPassThru.Output.Enable)[MOV(AFC56.inputbuffer[2],AFC56.ModbusPassThru.Input.BID) ,XIC(AFC56.ModbusPassThru.Input.BID.0) OTE(AFC56.ModbusPassThru.Input.MessagePresent) ,XIC(AFC56.ModbusPassThru.Input.BID.1) OTE(AFC56.ModbusPassThru.Input.Function_BitWrite) ,XIC(AFC56.ModbusPassThru.Input.BID.2) OTE(AFC56.ModbusPassThru.Input.OverflowError) ,XIC(AFC56.ModbusPassThru.Input.MessagePresent) XIO(AFC56.ModbusPassThru.Input.OverflowError) [MOV(AFC56.inputbuffer[3],AFC56.ModbusPassThru.Input.ModbusAddress) ,MOV(AFC56.inputbuffer[4],AFC56.ModbusPassThru.Input.RegisterCount) ,COP(AFC56.inputbuffer[5],AFC56.ModbusPassThru.Input.ReadData_Word[0],AFC56.ModbusPassThru.Input.RegisterCount) ] ];
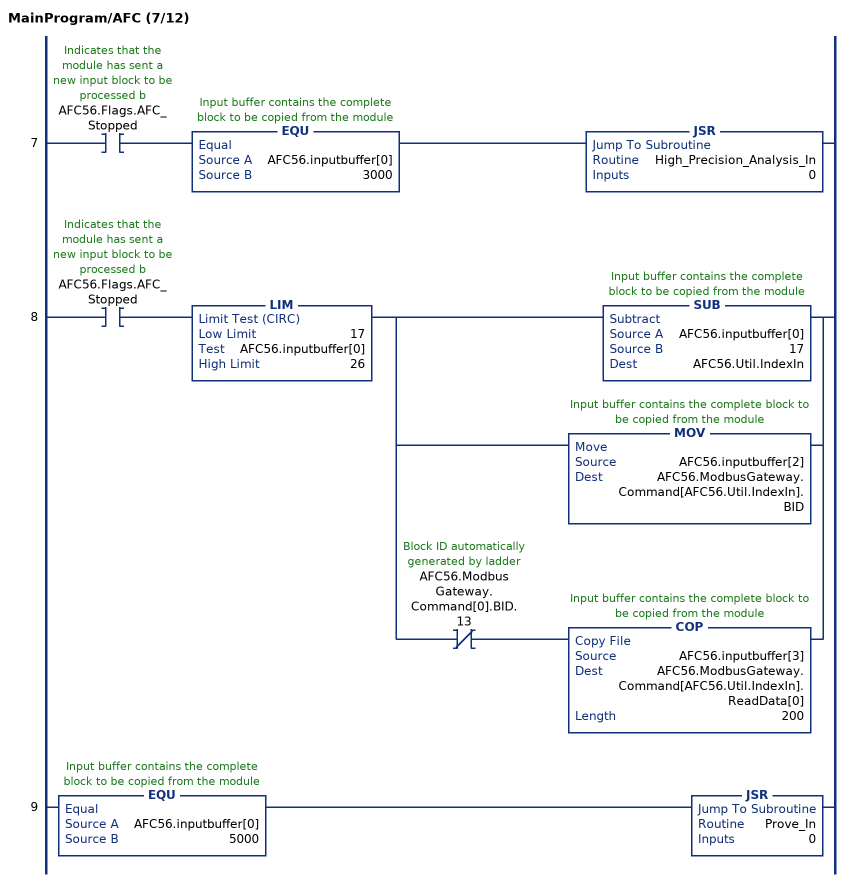
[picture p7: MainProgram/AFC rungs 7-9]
   7: XIC(AFC56.Flags.AFC_Stopped)EQU(AFC56.inputbuffer[0],3000)JSR(High_Precision_Analysis_In,0);
   8: XIC(AFC56.Flags.AFC_Stopped)LIM(17,AFC56.inputbuffer[0],26)[SUB(AFC56.inputbuffer[0],17,AFC56.Util.IndexIn) ,MOV(AFC56.inputbuffer[2],AFC56.ModbusGateway.Command[AFC56.Util.IndexIn].BID) ,XIO(AFC56.ModbusGateway.Command[0].BID.13) COP(AFC56.inputbuffer[3],AFC56.ModbusGateway.Command[AFC56.Util.IndexIn].ReadData[0],200) ];
   9: EQU(AFC56.inputbuffer[0],5000)JSR(Prove_In,0);
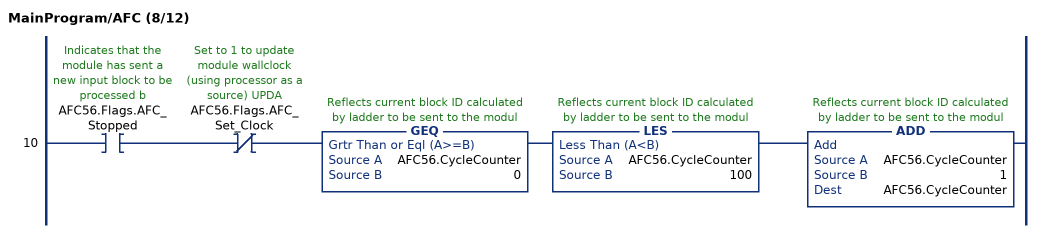
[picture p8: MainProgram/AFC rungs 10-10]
   10: XIC(AFC56.Flags.AFC_Stopped)XIO(AFC56.Flags.AFC_Set_Clock)GEQ(AFC56.CycleCounter,0)LES(AFC56.CycleCounter,100)ADD(AFC56.CycleCounter,1,AFC56.CycleCounter);
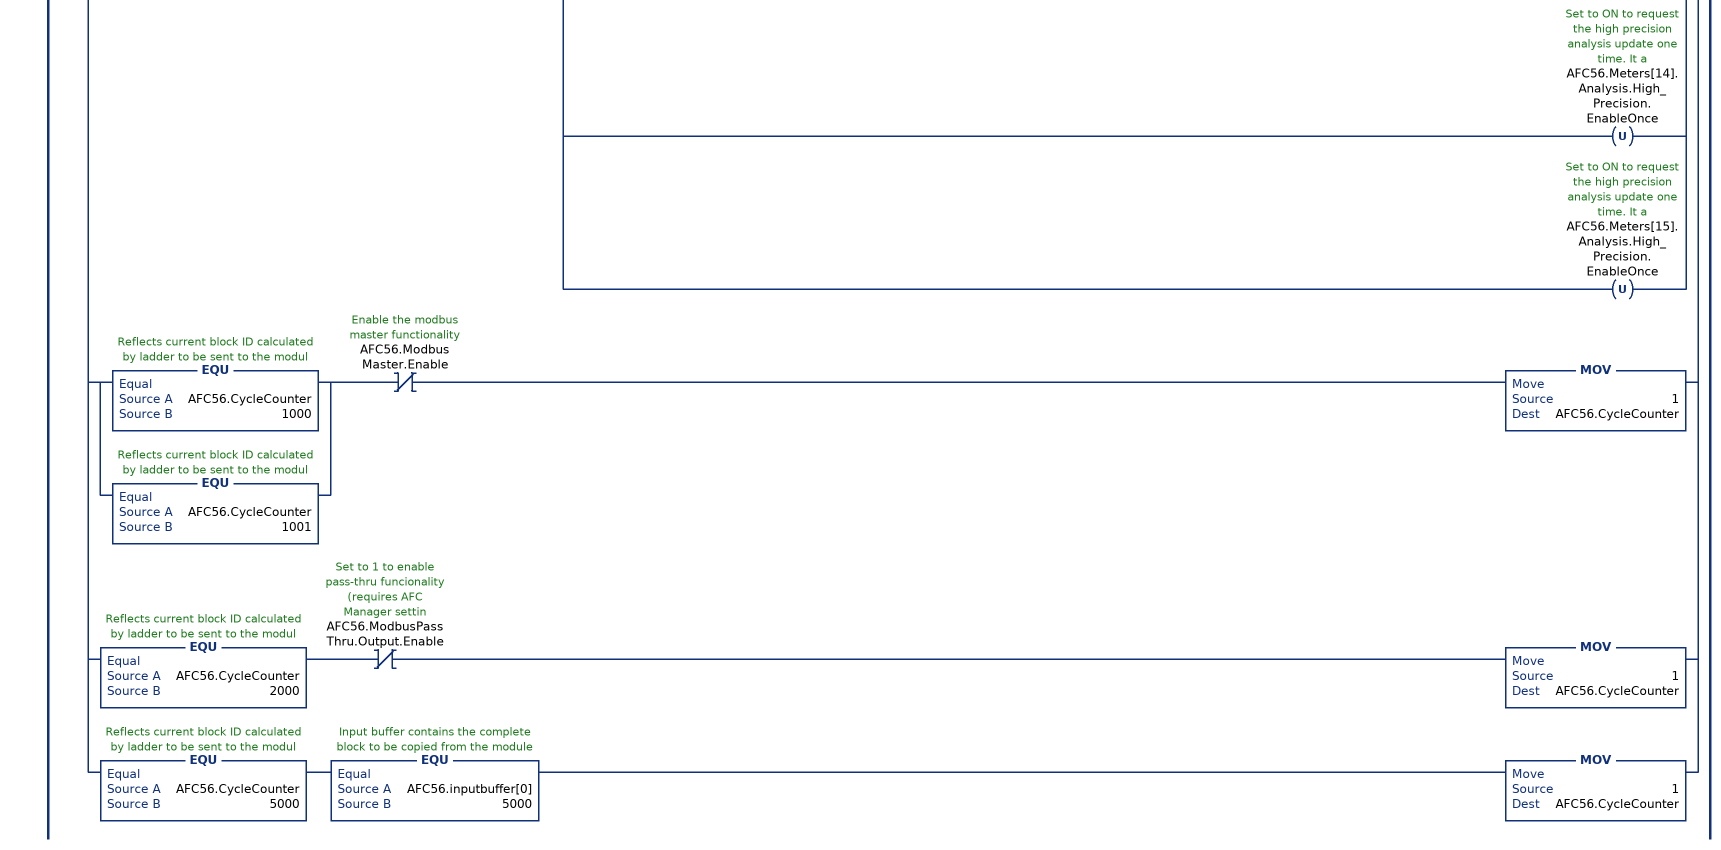
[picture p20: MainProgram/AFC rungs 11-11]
   11: XIC(AFC56.Flags.AFC_Stopped)[SUB(AFC56.Util.CycleCounterRollover,1,AFC56.Util.LastRegularBlockID) ,EQU(AFC56.CycleCounter,AFC56.Util.CycleCounterRollover) EQU(AFC56.inputbuffer[0],AFC56.Util.LastRegularBlockID) [XIO(AFC56.ModbusMaster.Enable) XIO(AFC56.ModbusPassThru.Output.Enable) [XIO(AFC56.Prove.Input.Prove_Enabled) MOV(1,AFC56.CycleCounter) ,XIC(AFC56.Prove.Input.Prove_Enabled) MOV(5000,AFC56.CycleCounter) ] ,XIC(AFC56.ModbusMaster.Enable) [MOV(1000,AFC56.CycleCounter) ,OTU(AFC56.ModbusMaster.Command[AFC56.ModbusMaster.CommandIndex].Output.Config.Enable) ] ,XIO(AFC56.ModbusMaster.Enable) XIC(AFC56.ModbusPassThru.Output.Enable) MOV(2000,AFC56.CycleCounter) ,XIO(AFC56.ModbusMaster.Enable) XIO(AFC56.ModbusPassThru.Output.Enable) [XIC(AFC56.Meters[0].Analysis.Status.Update) ,XIC(AFC56.Meters[1].Analysis.Status.Update) ,XIC(AFC56.Meters[2].Analysis.Status.Update) ,XIC(AFC56.Meters[3].Analysis.Status.Update) ,XIC(AFC56.Meters[4].Analysis.Status.Update) ,XIC(AFC56.Meters[5].Analysis.Status.Update) ,XIC(AFC56.Meters[6].Analysis.Status.Update) ,XIC(AFC56.Meters[7].Analysis.Status.Update) ,XIC(AFC56.Meters[8].Analysis.Status.Update) ,XIC(AFC56.Meters[9].Analysis.Status.Update) ,XIC(AFC56.Meters[10].Analysis.Status.Update) ,XIC(AFC56.Meters[11].Analysis.Status.Update) ,XIC(AFC56.Meters[12].Analysis.Status.Update) ,XIC(AFC56.Meters[13].Analysis.Status.Update) ,XIC(AFC56.Meters[14].Analysis.Status.Update) ,XIC(AFC56.Meters[15].Analysis.Status.Update) ] XIC(AFC56.inputbuffer[247].11) MOV(3000,AFC56.CycleCounter) ,XIO(AFC56.ModbusMaster.Enable) XIO(AFC56.ModbusPassThru.Output.Enable) [LES(AFC56.CycleCounter,3000) ,GRT(AFC56.CycleCounter,3004) ] [XIC(AFC56.Meters[0].Analysis.High_Precision.EnableOnce) ,XIC(AFC56.Meters[1].Analysis.High_Precision.EnableOnce) ,XIC(AFC56.Meters[2].Analysis.High_Precision.EnableOnce) ,XIC(AFC56.Meters[3].Analysis.High_Precision.EnableOnce) ,XIC(AFC56.Meters[4].Analysis.High_Precision.EnableOnce) ,XIC(AFC56.Meters[5].Analysis.High_Precision.EnableOnce) ,XIC(AFC56.Meters[6].Analysis.High_Precision.EnableOnce) ,XIC(AFC56.Meters[7].Analysis.High_Precision.EnableOnce) ,XIC(AFC56.Meters[8].Analysis.High_Precision.EnableOnce) ,XIC(AFC56.Meters[9].Analysis.High_Precision.EnableOnce) ,XIC(AFC56.Meters[10].Analysis.High_Precision.EnableOnce) ,XIC(AFC56.Meters[11].Analysis.High_Precision.EnableOnce) ,XIC(AFC56.Meters[12].Analysis.High_Precision.EnableOnce) ,XIC(AFC56.Meters[13].Analysis.High_Precision.EnableOnce) ,XIC(AFC56.Meters[13].Analysis.High_Precision.EnableOnce) ,XIC(AFC56.Meters[14].Analysis.High_Precision.EnableOnce) ,XIC(AFC56.Meters[15].Analysis.High_Precision.EnableOnce) ] XIC(AFC56.inputbuffer[247].11) MOV(3001,AFC56.CycleCounter) ] ,EQU(AFC56.CycleCounter,1000) EQU(AFC56.inputbuffer[0],1000) [MOV(1001,AFC56.CycleCounter) ,OTL(AFC56.ModbusMaster.Command[AFC56.ModbusMaster.CommandIndex].Output.Config.Enable) ] ,EQU(AFC56.CycleCounter,1001) EQU(AFC56.inputbuffer[0],1001) [XIC(AFC56.ModbusPassThru.Output.Enable) MOV(2000,AFC56.CycleCounter) ,XIO(AFC56.ModbusPassThru.Output.Enable) MOV(1,AFC56.CycleCounter) ] ,EQU(AFC56.CycleCounter,2000) EQU(AFC56.inputbuffer[0],2000) MOV(1,AFC56.CycleCounter) ,EQU(AFC56.CycleCounter,3001) EQU(AFC56.inputbuffer[0],3001) MOV(3002,AFC56.CycleCounter) ,EQU(AFC56.CycleCounter,3002) EQU(AFC56.inputbuffer[0],3002) MOV(3003,AFC56.CycleCounter) ,EQU(AFC56.CycleCounter,3003) EQU(AFC56.inputbuffer[0],3003) MOV(3004,AFC56.CycleCounter) ,EQU(AFC56.CycleCounter,3004) EQU(AFC56.inputbuffer[0],3004) [XIO(AFC56.Prove.Input.Prove_Enabled) MOV(1,AFC56.CycleCounter) ,XIC(AFC56.Prove.Input.Prove_Enabled) MOV(5000,AFC56.CycleCounter) ,OTU(AFC56.Meters[0].Analysis.High_Precision.EnableOnce) ,OTU(AFC56.Meters[1].Analysis.High_Precision.EnableOnce) ,OTU(AFC56.Meters[2].Analysis.High_Precision.EnableOnce) ,OTU(AFC56.Meters[3].Analysis.High_Precision.EnableOnce) ,OTU(AFC56.Meters[4].Analysis.High_Precision.EnableOnce) ,OTU(AFC56.Meters[5].Analysis.High_Precision.EnableOnce) ,OTU(AFC56.Meters[6].Analysis.High_Precision.EnableOnce) ,OTU(AFC56.Meters[7].Analysis.High_Precision.EnableOnce) ,OTU(AFC56.Meters[8].Analysis.High_Precision.EnableOnce) ,OTU(AFC56.Meters[9].Analysis.High_Precision.EnableOnce) ,OTU(AFC56.Meters[10].Analysis.High_Precision.EnableOnce) ,OTU(AFC56.Meters[11].Analysis.High_Precision.EnableOnce) ,OTU(AFC56.Meters[12].Analysis.High_Precision.EnableOnce) ,OTU(AFC56.Meters[13].Analysis.High_Precision.EnableOnce) ,OTU(AFC56.Meters[13].Analysis.High_Precision.EnableOnce) ,OTU(AFC56.Meters[14].Analysis.High_Precision.EnableOnce) ,OTU(AFC56.Meters[15].Analysis.High_Precision.EnableOnce) ] ,EQU(AFC56.CycleCounter,3000) EQU(AFC56.inputbuffer[0],3000) [MOV(1,AFC56.CycleCounter) ,OTU(AFC56.Meters[0].Analysis.High_Precision.EnableOnce) ,OTU(AFC56.Meters[1].Analysis.High_Precision.EnableOnce) ,OTU(AFC56.Meters[2].Analysis.High_Precision.EnableOnce) ,OTU(AFC56.Meters[3].Analysis.High_Precision.EnableOnce) ,OTU(AFC56.Meters[4].Analysis.High_Precision.EnableOnce) ,OTU(AFC56.Meters[5].Analysis.High_Precision.EnableOnce) ,OTU(AFC56.Meters[6].Analysis.High_Precision.EnableOnce) ,OTU(AFC56.Meters[7].Analysis.High_Precision.EnableOnce) ,OTU(AFC56.Meters[8].Analysis.High_Precision.EnableOnce) ,OTU(AFC56.Meters[9].Analysis.High_Precision.EnableOnce) ,OTU(AFC56.Meters[10].Analysis.High_Precision.EnableOnce) ,OTU(AFC56.Meters[11].Analysis.High_Precision.EnableOnce) ,OTU(AFC56.Meters[12].Analysis.High_Precision.EnableOnce) ,OTU(AFC56.Meters[13].Analysis.High_Precision.EnableOnce) ,OTU(AFC56.Meters[13].Analysis.High_Precision.EnableOnce) ,OTU(AFC56.Meters[14].Analysis.High_Precision.EnableOnce) ,OTU(AFC56.Meters[15].Analysis.High_Precision.EnableOnce) ] ,[EQU(AFC56.CycleCounter,1000) ,EQU(AFC56.CycleCounter,1001) ] XIO(AFC56.ModbusMaster.Enable) MOV(1,AFC56.CycleCounter) ,EQU(AFC56.CycleCounter,2000) XIO(AFC56.ModbusPassThru.Output.Enable) MOV(1,AFC56.CycleCounter) ,EQU(AFC56.CycleCounter,5000) EQU(AFC56.inputbuffer[0],5000) MOV(1,AFC56.CycleCounter) ];
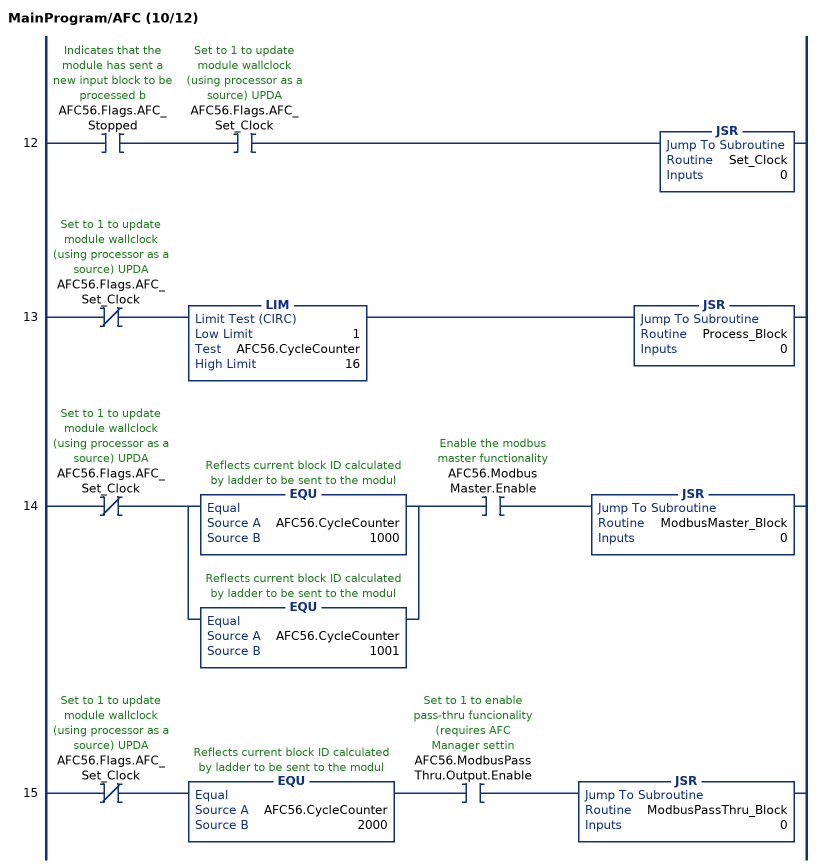
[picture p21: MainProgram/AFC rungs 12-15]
   12: XIC(AFC56.Flags.AFC_Stopped)XIC(AFC56.Flags.AFC_Set_Clock)JSR(Set_Clock,0);
   13: XIO(AFC56.Flags.AFC_Set_Clock)LIM(1,AFC56.CycleCounter,16)JSR(Process_Block,0);
   14: XIO(AFC56.Flags.AFC_Set_Clock)[EQU(AFC56.CycleCounter,1000) ,EQU(AFC56.CycleCounter,1001) ]XIC(AFC56.ModbusMaster.Enable)JSR(ModbusMaster_Block,0);
   15: XIO(AFC56.Flags.AFC_Set_Clock)EQU(AFC56.CycleCounter,2000)XIC(AFC56.ModbusPassThru.Output.Enable)JSR(ModbusPassThru_Block,0);
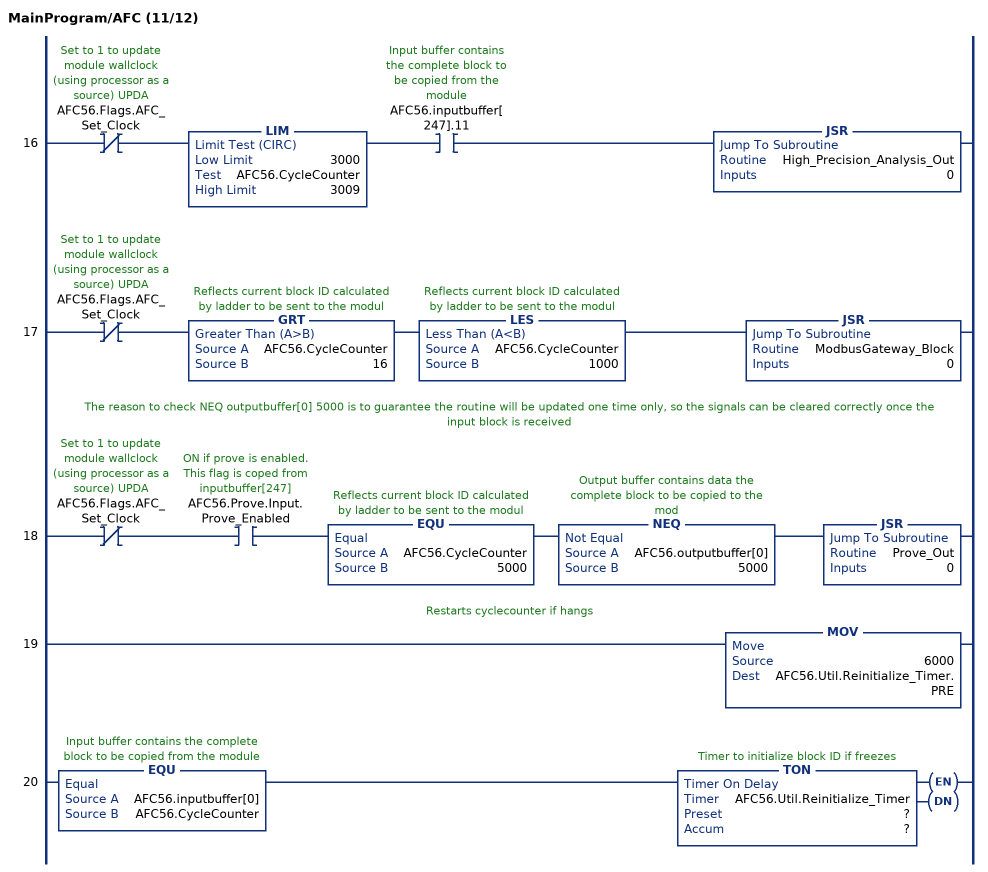
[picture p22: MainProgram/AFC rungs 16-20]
   16: XIO(AFC56.Flags.AFC_Set_Clock)LIM(3000,AFC56.CycleCounter,3009)XIC(AFC56.inputbuffer[247].11)JSR(High_Precision_Analysis_Out,0);
   17: XIO(AFC56.Flags.AFC_Set_Clock)GRT(AFC56.CycleCounter,16)LES(AFC56.CycleCounter,1000)JSR(ModbusGateway_Block,0);
   // The reason to check NEQ outputbuffer[0] 5000 is to guarantee the routine will be updated one time only, so the signals can be cleared correctly once the input block is received
   18: XIO(AFC56.Flags.AFC_Set_Clock)XIC(AFC56.Prove.Input.Prove_Enabled)EQU(AFC56.CycleCounter,5000)NEQ(AFC56.outputbuffer[0],5000)JSR(Prove_Out,0);
   // Restarts cyclecounter if hangs
   19: MOV(6000,AFC56.Util.Reinitialize_Timer.PRE);
   20: EQU(AFC56.inputbuffer[0],AFC56.CycleCounter)TON(AFC56.Util.Reinitialize_Timer,?,?);
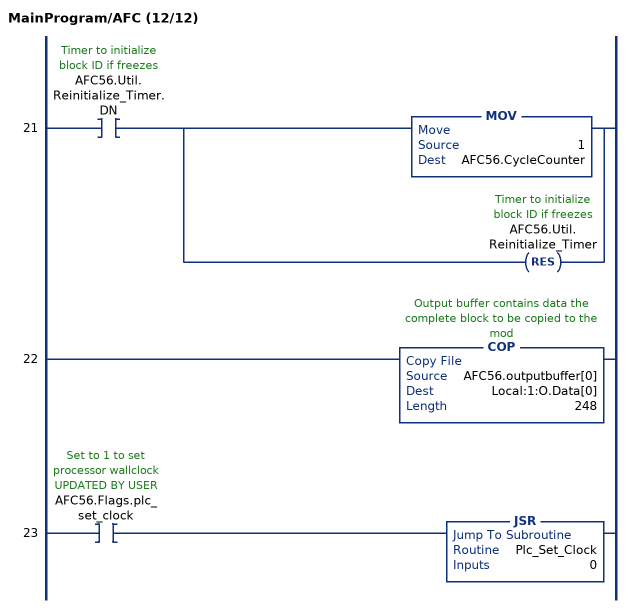
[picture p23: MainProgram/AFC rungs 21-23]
   21: XIC(AFC56.Util.Reinitialize_Timer.DN)[MOV(1,AFC56.CycleCounter) ,RES(AFC56.Util.Reinitialize_Timer) ];
   22: COP(AFC56.outputbuffer[0],Local:1:O.Data[0],248);
   23: XIC(AFC56.Flags.plc_set_clock)JSR(Plc_Set_Clock,0);
END_ROUTINE

ROUTINE High_Precision_Analysis_In   (* ladder *)
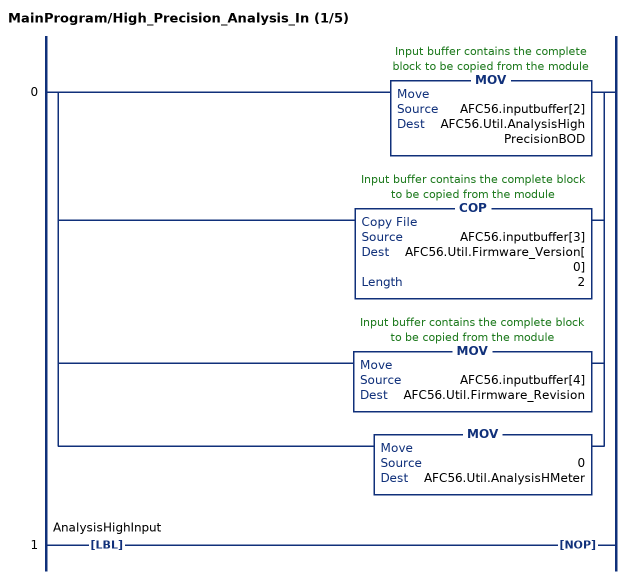
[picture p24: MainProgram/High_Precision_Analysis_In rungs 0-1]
   0: [MOV(AFC56.inputbuffer[2],AFC56.Util.AnalysisHighPrecisionBOD) ,COP(AFC56.inputbuffer[3],AFC56.Util.Firmware_Version[0],2) ,MOV(AFC56.inputbuffer[4],AFC56.Util.Firmware_Revision) ,MOV(0,AFC56.Util.AnalysisHMeter) ];
   1: LBL(AnalysisHighInput)NOP();
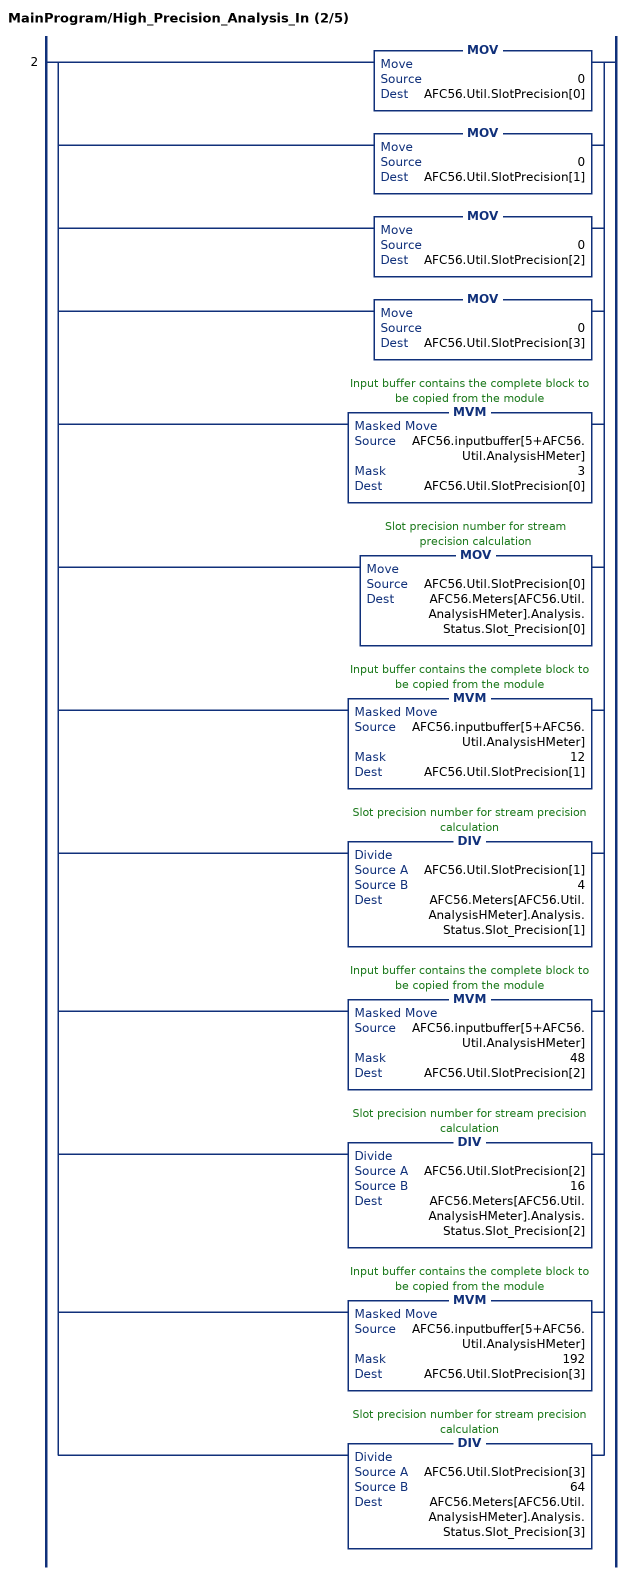
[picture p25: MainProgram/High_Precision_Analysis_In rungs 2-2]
   2: [MOV(0,AFC56.Util.SlotPrecision[0]) ,MOV(0,AFC56.Util.SlotPrecision[1]) ,MOV(0,AFC56.Util.SlotPrecision[2]) ,MOV(0,AFC56.Util.SlotPrecision[3]) ,MVM(AFC56.inputbuffer[5+AFC56.Util.AnalysisHMeter],3,AFC56.Util.SlotPrecision[0]) ,MOV(AFC56.Util.SlotPrecision[0],AFC56.Meters[AFC56.Util.AnalysisHMeter].Analysis.Status.Slot_Precision[0]) ,MVM(AFC56.inputbuffer[5+AFC56.Util.AnalysisHMeter],12,AFC56.Util.SlotPrecision[1]) ,DIV(AFC56.Util.SlotPrecision[1],4,AFC56.Meters[AFC56.Util.AnalysisHMeter].Analysis.Status.Slot_Precision[1]) ,MVM(AFC56.inputbuffer[5+AFC56.Util.AnalysisHMeter],48,AFC56.Util.SlotPrecision[2]) ,DIV(AFC56.Util.SlotPrecision[2],16,AFC56.Meters[AFC56.Util.AnalysisHMeter].Analysis.Status.Slot_Precision[2]) ,MVM(AFC56.inputbuffer[5+AFC56.Util.AnalysisHMeter],192,AFC56.Util.SlotPrecision[3]) ,DIV(AFC56.Util.SlotPrecision[3],64,AFC56.Meters[AFC56.Util.AnalysisHMeter].Analysis.Status.Slot_Precision[3]) ];
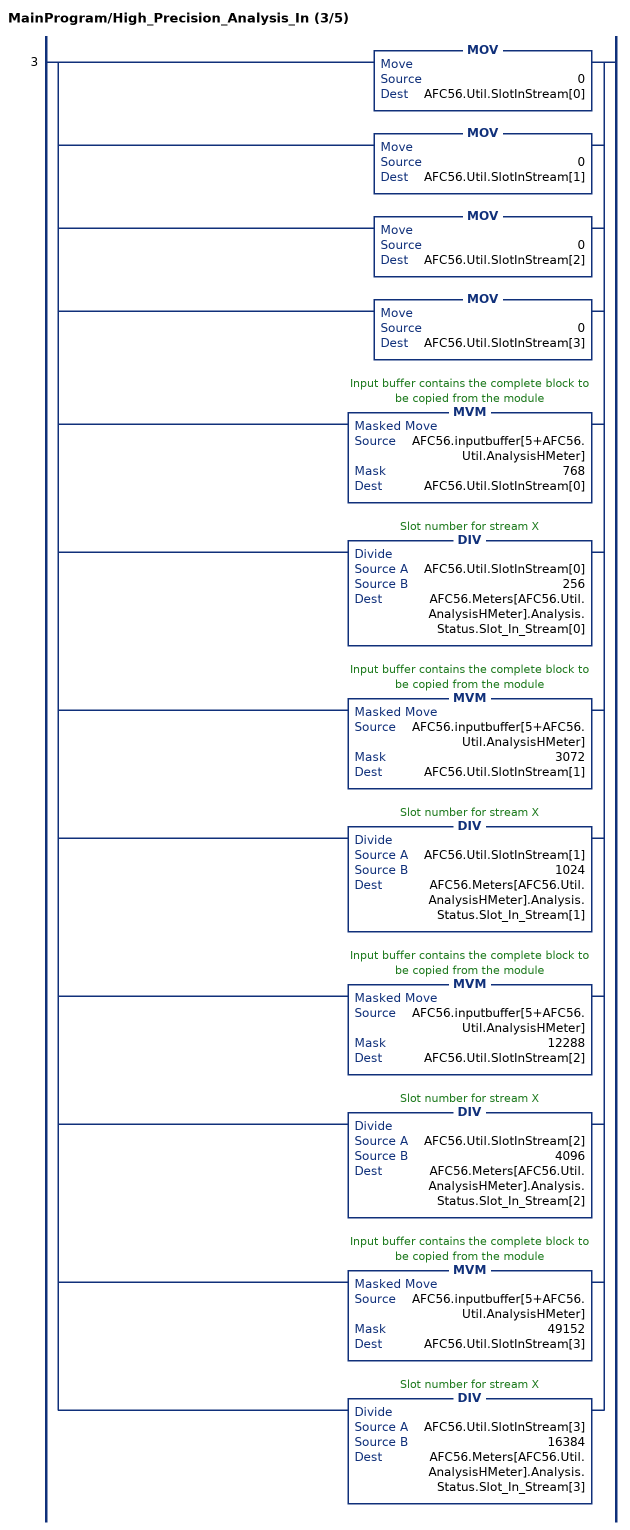
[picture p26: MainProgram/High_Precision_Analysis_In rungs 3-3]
   3: [MOV(0,AFC56.Util.SlotInStream[0]) ,MOV(0,AFC56.Util.SlotInStream[1]) ,MOV(0,AFC56.Util.SlotInStream[2]) ,MOV(0,AFC56.Util.SlotInStream[3]) ,MVM(AFC56.inputbuffer[5+AFC56.Util.AnalysisHMeter],768,AFC56.Util.SlotInStream[0]) ,DIV(AFC56.Util.SlotInStream[0],256,AFC56.Meters[AFC56.Util.AnalysisHMeter].Analysis.Status.Slot_In_Stream[0]) ,MVM(AFC56.inputbuffer[5+AFC56.Util.AnalysisHMeter],3072,AFC56.Util.SlotInStream[1]) ,DIV(AFC56.Util.SlotInStream[1],1024,AFC56.Meters[AFC56.Util.AnalysisHMeter].Analysis.Status.Slot_In_Stream[1]) ,MVM(AFC56.inputbuffer[5+AFC56.Util.AnalysisHMeter],12288,AFC56.Util.SlotInStream[2]) ,DIV(AFC56.Util.SlotInStream[2],4096,AFC56.Meters[AFC56.Util.AnalysisHMeter].Analysis.Status.Slot_In_Stream[2]) ,MVM(AFC56.inputbuffer[5+AFC56.Util.AnalysisHMeter],49152,AFC56.Util.SlotInStream[3]) ,DIV(AFC56.Util.SlotInStream[3],16384,AFC56.Meters[AFC56.Util.AnalysisHMeter].Analysis.Status.Slot_In_Stream[3]) ];
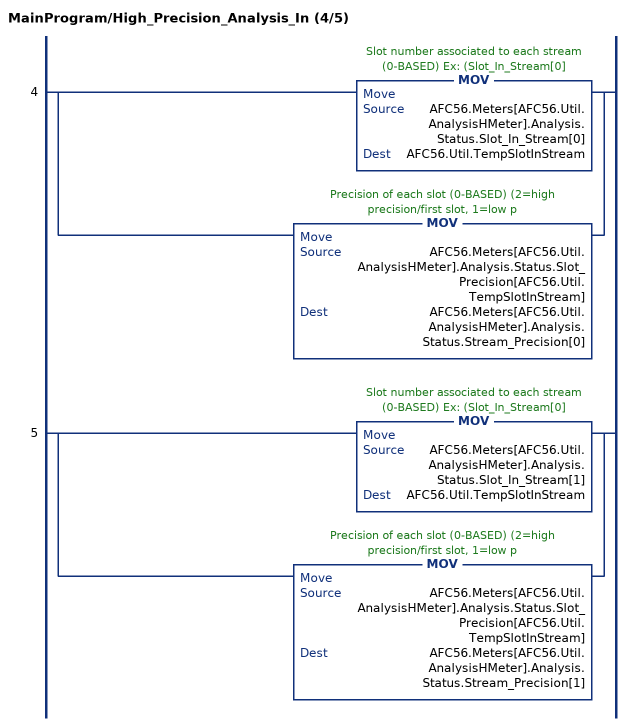
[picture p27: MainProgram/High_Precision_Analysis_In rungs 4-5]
   4: [MOV(AFC56.Meters[AFC56.Util.AnalysisHMeter].Analysis.Status.Slot_In_Stream[0],AFC56.Util.TempSlotInStream) ,MOV(AFC56.Meters[AFC56.Util.AnalysisHMeter].Analysis.Status.Slot_Precision[AFC56.Util.TempSlotInStream],AFC56.Meters[AFC56.Util.AnalysisHMeter].Analysis.Status.Stream_Precision[0]) ];
   5: [MOV(AFC56.Meters[AFC56.Util.AnalysisHMeter].Analysis.Status.Slot_In_Stream[1],AFC56.Util.TempSlotInStream) ,MOV(AFC56.Meters[AFC56.Util.AnalysisHMeter].Analysis.Status.Slot_Precision[AFC56.Util.TempSlotInStream],AFC56.Meters[AFC56.Util.AnalysisHMeter].Analysis.Status.Stream_Precision[1]) ];
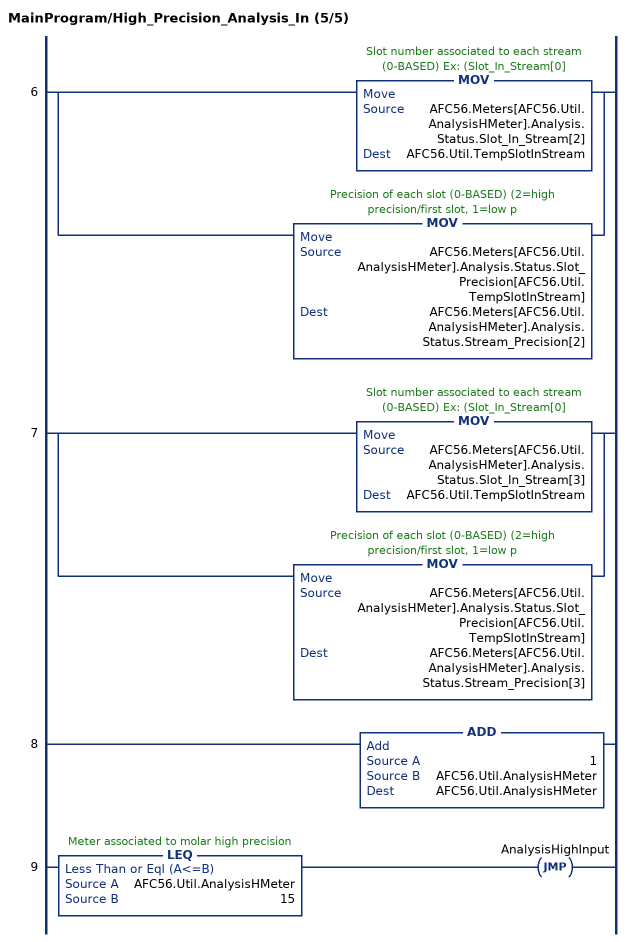
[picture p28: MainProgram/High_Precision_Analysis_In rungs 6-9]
   6: [MOV(AFC56.Meters[AFC56.Util.AnalysisHMeter].Analysis.Status.Slot_In_Stream[2],AFC56.Util.TempSlotInStream) ,MOV(AFC56.Meters[AFC56.Util.AnalysisHMeter].Analysis.Status.Slot_Precision[AFC56.Util.TempSlotInStream],AFC56.Meters[AFC56.Util.AnalysisHMeter].Analysis.Status.Stream_Precision[2]) ];
   7: [MOV(AFC56.Meters[AFC56.Util.AnalysisHMeter].Analysis.Status.Slot_In_Stream[3],AFC56.Util.TempSlotInStream) ,MOV(AFC56.Meters[AFC56.Util.AnalysisHMeter].Analysis.Status.Slot_Precision[AFC56.Util.TempSlotInStream],AFC56.Meters[AFC56.Util.AnalysisHMeter].Analysis.Status.Stream_Precision[3]) ];
   8: ADD(1,AFC56.Util.AnalysisHMeter,AFC56.Util.AnalysisHMeter);
   9: LEQ(AFC56.Util.AnalysisHMeter,15)JMP(AnalysisHighInput);
END_ROUTINE

ROUTINE High_Precision_Analysis_Out   (* ladder *)
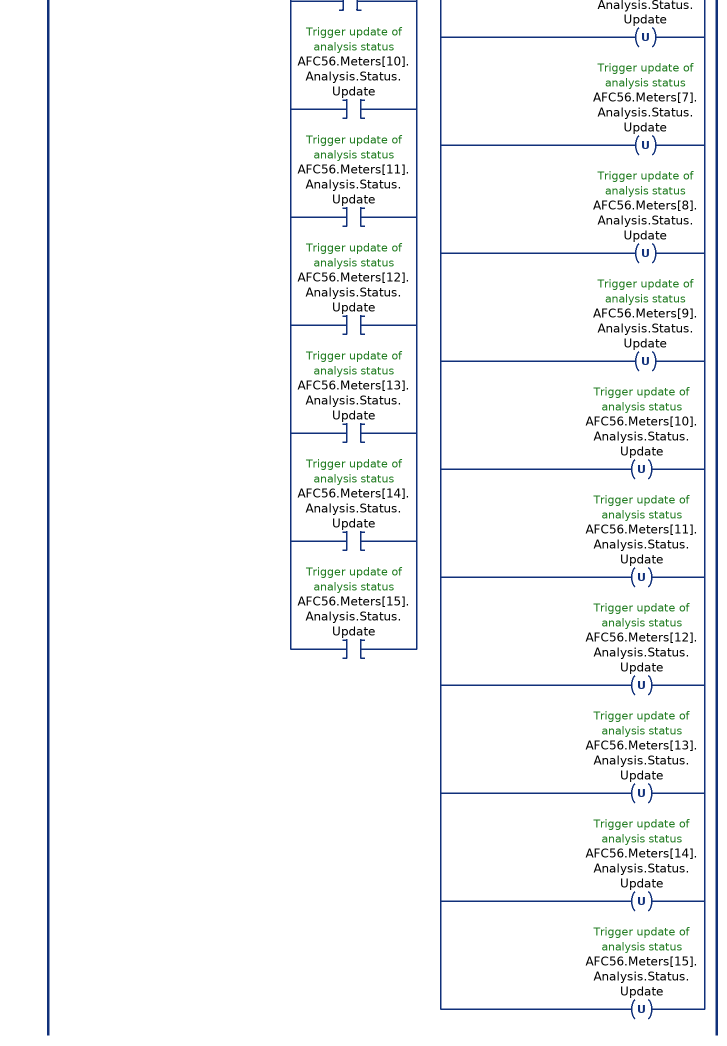
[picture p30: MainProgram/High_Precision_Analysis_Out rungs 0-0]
   0: EQU(AFC56.CycleCounter,3000)[XIC(AFC56.Meters[0].Analysis.Status.Update) ,XIC(AFC56.Meters[1].Analysis.Status.Update) ,XIC(AFC56.Meters[2].Analysis.Status.Update) ,XIC(AFC56.Meters[3].Analysis.Status.Update) ,XIC(AFC56.Meters[4].Analysis.Status.Update) ,XIC(AFC56.Meters[5].Analysis.Status.Update) ,XIC(AFC56.Meters[6].Analysis.Status.Update) ,XIC(AFC56.Meters[7].Analysis.Status.Update) ,XIC(AFC56.Meters[8].Analysis.Status.Update) ,XIC(AFC56.Meters[9].Analysis.Status.Update) ,XIC(AFC56.Meters[10].Analysis.Status.Update) ,XIC(AFC56.Meters[11].Analysis.Status.Update) ,XIC(AFC56.Meters[12].Analysis.Status.Update) ,XIC(AFC56.Meters[13].Analysis.Status.Update) ,XIC(AFC56.Meters[14].Analysis.Status.Update) ,XIC(AFC56.Meters[15].Analysis.Status.Update) ][MOV(11553,AFC56.Util.AnalysisHighPrecisionBID_Update) ,MOV(49,AFC56.outputbuffer[1]) ,MOV(AFC56.Util.AnalysisHighPrecisionBID_Update,AFC56.outputbuffer[2]) ,OTU(AFC56.Meters[0].Analysis.Status.Update) ,OTU(AFC56.Meters[1].Analysis.Status.Update) ,OTU(AFC56.Meters[2].Analysis.Status.Update) ,OTU(AFC56.Meters[3].Analysis.Status.Update) ,OTU(AFC56.Meters[4].Analysis.Status.Update) ,OTU(AFC56.Meters[5].Analysis.Status.Update) ,OTU(AFC56.Meters[6].Analysis.Status.Update) ,OTU(AFC56.Meters[7].Analysis.Status.Update) ,OTU(AFC56.Meters[8].Analysis.Status.Update) ,OTU(AFC56.Meters[9].Analysis.Status.Update) ,OTU(AFC56.Meters[10].Analysis.Status.Update) ,OTU(AFC56.Meters[11].Analysis.Status.Update) ,OTU(AFC56.Meters[12].Analysis.Status.Update) ,OTU(AFC56.Meters[13].Analysis.Status.Update) ,OTU(AFC56.Meters[14].Analysis.Status.Update) ,OTU(AFC56.Meters[15].Analysis.Status.Update) ];
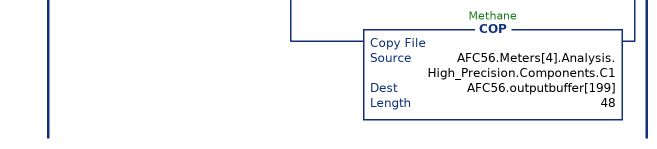
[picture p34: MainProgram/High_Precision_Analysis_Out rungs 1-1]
   1: EQU(AFC56.CycleCounter,3001)[MOV(245,AFC56.outputbuffer[1]) ,MOV(0,AFC56.Util.Meter_HighAnalysis) ,CPT(AFC56.Util.AnalysisHighPrecisionBID[0],AFC56.Meters[0].Analysis.High_Precision.Stream*32+AFC56.Util.Meter_HighAnalysis+1+11264) ,XIO(AFC56.Meters[0].Analysis.High_Precision.EnableOnce) OTE(AFC56.Util.AnalysisHighPrecisionBID[0].8) ,MOV(AFC56.Util.AnalysisHighPrecisionBID[0],AFC56.outputbuffer[2]) ,COP(AFC56.Meters[0].Analysis.High_Precision.Components.C1,AFC56.outputbuffer[3],48) ,MOV(1,AFC56.Util.Meter_HighAnalysis) ,CPT(AFC56.Util.AnalysisHighPrecisionBID[1],AFC56.Meters[1].Analysis.High_Precision.Stream*32+AFC56.Util.Meter_HighAnalysis+1+11264) ,XIO(AFC56.Meters[1].Analysis.High_Precision.EnableOnce) OTE(AFC56.Util.AnalysisHighPrecisionBID[1].8) ,MOV(AFC56.Util.AnalysisHighPrecisionBID[1],AFC56.outputbuffer[51]) ,COP(AFC56.Meters[1].Analysis.High_Precision.Components.C1,AFC56.outputbuffer[52],48) ,MOV(2,AFC56.Util.Meter_HighAnalysis) ,CPT(AFC56.Util.AnalysisHighPrecisionBID[2],AFC56.Meters[2].Analysis.High_Precision.Stream*32+AFC56.Util.Meter_HighAnalysis+1+11264) ,XIO(AFC56.Meters[2].Analysis.High_Precision.EnableOnce) OTE(AFC56.Util.AnalysisHighPrecisionBID[2].8) ,MOV(AFC56.Util.AnalysisHighPrecisionBID[2],AFC56.outputbuffer[100]) ,COP(AFC56.Meters[2].Analysis.High_Precision.Components.C1,AFC56.outputbuffer[101],48) ,MOV(3,AFC56.Util.Meter_HighAnalysis) ,CPT(AFC56.Util.AnalysisHighPrecisionBID[3],AFC56.Meters[3].Analysis.High_Precision.Stream*32+AFC56.Util.Meter_HighAnalysis+1+11264) ,XIO(AFC56.Meters[3].Analysis.High_Precision.EnableOnce) OTE(AFC56.Util.AnalysisHighPrecisionBID[3].8) ,MOV(AFC56.Util.AnalysisHighPrecisionBID[3],AFC56.outputbuffer[149]) ,COP(AFC56.Meters[3].Analysis.High_Precision.Components.C1,AFC56.outputbuffer[150],48) ,MOV(4,AFC56.Util.Meter_HighAnalysis) ,CPT(AFC56.Util.AnalysisHighPrecisionBID[4],AFC56.Meters[4].Analysis.High_Precision.Stream*32+AFC56.Util.Meter_HighAnalysis+1+11264) ,XIO(AFC56.Meters[4].Analysis.High_Precision.EnableOnce) OTE(AFC56.Util.AnalysisHighPrecisionBID[4].8) ,MOV(AFC56.Util.AnalysisHighPrecisionBID[4],AFC56.outputbuffer[198]) ,COP(AFC56.Meters[4].Analysis.High_Precision.Components.C1,AFC56.outputbuffer[199],48) ];
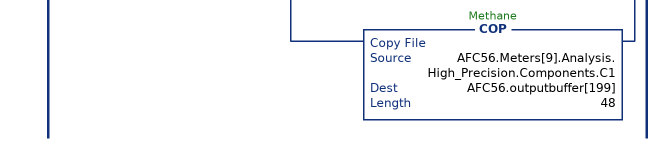
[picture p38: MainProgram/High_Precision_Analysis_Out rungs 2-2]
   2: EQU(AFC56.CycleCounter,3002)[MOV(245,AFC56.outputbuffer[1]) ,MOV(5,AFC56.Util.Meter_HighAnalysis) ,CPT(AFC56.Util.AnalysisHighPrecisionBID[5],AFC56.Meters[5].Analysis.High_Precision.Stream*32+AFC56.Util.Meter_HighAnalysis+1+11264) ,XIO(AFC56.Meters[5].Analysis.High_Precision.EnableOnce) OTE(AFC56.Util.AnalysisHighPrecisionBID[5].8) ,MOV(AFC56.Util.AnalysisHighPrecisionBID[5],AFC56.outputbuffer[2]) ,COP(AFC56.Meters[5].Analysis.High_Precision.Components.C1,AFC56.outputbuffer[3],48) ,MOV(6,AFC56.Util.Meter_HighAnalysis) ,CPT(AFC56.Util.AnalysisHighPrecisionBID[6],AFC56.Meters[6].Analysis.High_Precision.Stream*32+AFC56.Util.Meter_HighAnalysis+1+11264) ,XIO(AFC56.Meters[6].Analysis.High_Precision.EnableOnce) OTE(AFC56.Util.AnalysisHighPrecisionBID[6].8) ,MOV(AFC56.Util.AnalysisHighPrecisionBID[6],AFC56.outputbuffer[51]) ,COP(AFC56.Meters[6].Analysis.High_Precision.Components.C1,AFC56.outputbuffer[52],48) ,MOV(7,AFC56.Util.Meter_HighAnalysis) ,CPT(AFC56.Util.AnalysisHighPrecisionBID[7],AFC56.Meters[7].Analysis.High_Precision.Stream*32+AFC56.Util.Meter_HighAnalysis+1+11264) ,XIO(AFC56.Meters[7].Analysis.High_Precision.EnableOnce) OTE(AFC56.Util.AnalysisHighPrecisionBID[7].8) ,MOV(AFC56.Util.AnalysisHighPrecisionBID[7],AFC56.outputbuffer[100]) ,COP(AFC56.Meters[7].Analysis.High_Precision.Components.C1,AFC56.outputbuffer[101],48) ,MOV(8,AFC56.Util.Meter_HighAnalysis) ,CPT(AFC56.Util.AnalysisHighPrecisionBID[8],AFC56.Meters[8].Analysis.High_Precision.Stream*32+AFC56.Util.Meter_HighAnalysis+1+11264) ,XIO(AFC56.Meters[8].Analysis.High_Precision.EnableOnce) OTE(AFC56.Util.AnalysisHighPrecisionBID[8].8) ,MOV(AFC56.Util.AnalysisHighPrecisionBID[8],AFC56.outputbuffer[149]) ,COP(AFC56.Meters[8].Analysis.High_Precision.Components.C1,AFC56.outputbuffer[150],48) ,MOV(9,AFC56.Util.Meter_HighAnalysis) ,CPT(AFC56.Util.AnalysisHighPrecisionBID[9],AFC56.Meters[9].Analysis.High_Precision.Stream*32+AFC56.Util.Meter_HighAnalysis+1+11264) ,XIO(AFC56.Meters[9].Analysis.High_Precision.EnableOnce) OTE(AFC56.Util.AnalysisHighPrecisionBID[9].8) ,MOV(AFC56.Util.AnalysisHighPrecisionBID[9],AFC56.outputbuffer[198]) ,COP(AFC56.Meters[9].Analysis.High_Precision.Components.C1,AFC56.outputbuffer[199],48) ];
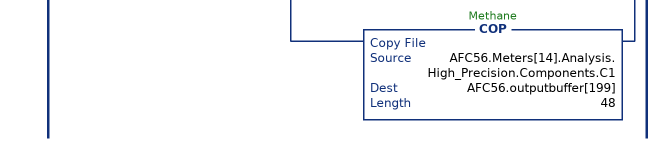
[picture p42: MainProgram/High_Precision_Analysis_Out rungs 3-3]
   3: EQU(AFC56.CycleCounter,3003)[MOV(245,AFC56.outputbuffer[1]) ,MOV(10,AFC56.Util.Meter_HighAnalysis) ,CPT(AFC56.Util.AnalysisHighPrecisionBID[10],AFC56.Meters[10].Analysis.High_Precision.Stream*32+AFC56.Util.Meter_HighAnalysis+1+11264) ,XIO(AFC56.Meters[10].Analysis.High_Precision.EnableOnce) OTE(AFC56.Util.AnalysisHighPrecisionBID[10].8) ,MOV(AFC56.Util.AnalysisHighPrecisionBID[10],AFC56.outputbuffer[2]) ,COP(AFC56.Meters[10].Analysis.High_Precision.Components.C1,AFC56.outputbuffer[3],48) ,MOV(11,AFC56.Util.Meter_HighAnalysis) ,CPT(AFC56.Util.AnalysisHighPrecisionBID[11],AFC56.Meters[11].Analysis.High_Precision.Stream*32+AFC56.Util.Meter_HighAnalysis+1+11264) ,XIO(AFC56.Meters[11].Analysis.High_Precision.EnableOnce) OTE(AFC56.Util.AnalysisHighPrecisionBID[11].8) ,MOV(AFC56.Util.AnalysisHighPrecisionBID[11],AFC56.outputbuffer[51]) ,COP(AFC56.Meters[11].Analysis.High_Precision.Components.C1,AFC56.outputbuffer[52],48) ,MOV(12,AFC56.Util.Meter_HighAnalysis) ,CPT(AFC56.Util.AnalysisHighPrecisionBID[12],AFC56.Meters[12].Analysis.High_Precision.Stream*32+AFC56.Util.Meter_HighAnalysis+1+11264) ,XIO(AFC56.Meters[12].Analysis.High_Precision.EnableOnce) OTE(AFC56.Util.AnalysisHighPrecisionBID[12].8) ,MOV(AFC56.Util.AnalysisHighPrecisionBID[12],AFC56.outputbuffer[100]) ,COP(AFC56.Meters[12].Analysis.High_Precision.Components.C1,AFC56.outputbuffer[101],48) ,MOV(13,AFC56.Util.Meter_HighAnalysis) ,CPT(AFC56.Util.AnalysisHighPrecisionBID[13],AFC56.Meters[13].Analysis.High_Precision.Stream*32+AFC56.Util.Meter_HighAnalysis+1+11264) ,XIO(AFC56.Meters[13].Analysis.High_Precision.EnableOnce) OTE(AFC56.Util.AnalysisHighPrecisionBID[13].8) ,MOV(AFC56.Util.AnalysisHighPrecisionBID[13],AFC56.outputbuffer[149]) ,COP(AFC56.Meters[13].Analysis.High_Precision.Components.C1,AFC56.outputbuffer[150],48) ,MOV(14,AFC56.Util.Meter_HighAnalysis) ,CPT(AFC56.Util.AnalysisHighPrecisionBID[14],AFC56.Meters[14].Analysis.High_Precision.Stream*32+AFC56.Util.Meter_HighAnalysis+1+11264) ,XIO(AFC56.Meters[14].Analysis.High_Precision.EnableOnce) OTE(AFC56.Util.AnalysisHighPrecisionBID[14].8) ,MOV(AFC56.Util.AnalysisHighPrecisionBID[14],AFC56.outputbuffer[198]) ,COP(AFC56.Meters[14].Analysis.High_Precision.Components.C1,AFC56.outputbuffer[199],48) ];
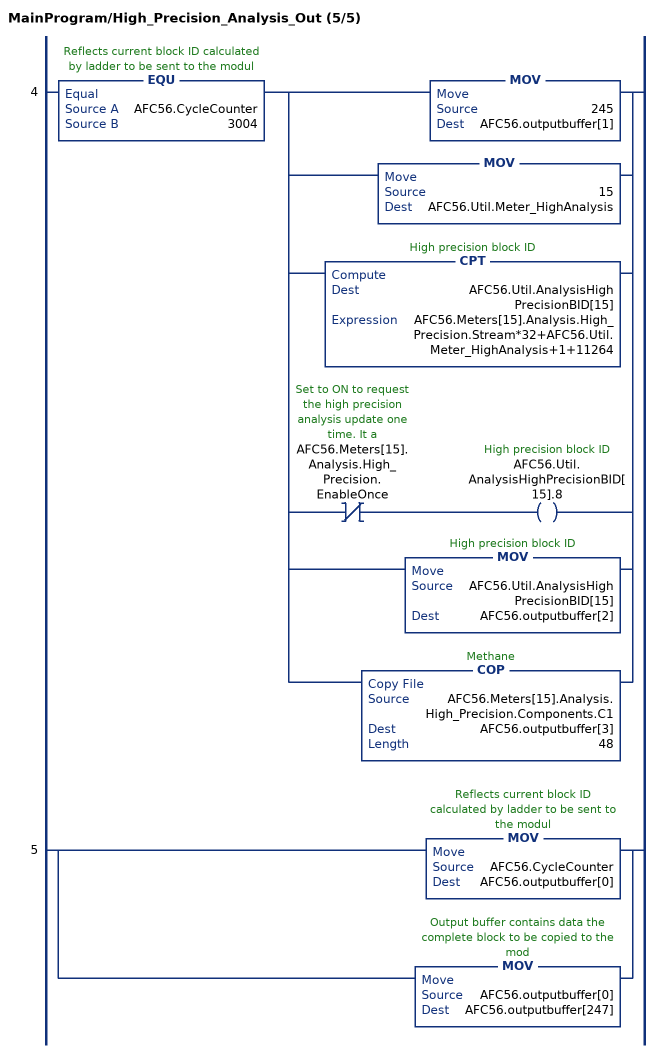
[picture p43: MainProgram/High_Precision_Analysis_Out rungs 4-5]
   4: EQU(AFC56.CycleCounter,3004)[MOV(245,AFC56.outputbuffer[1]) ,MOV(15,AFC56.Util.Meter_HighAnalysis) ,CPT(AFC56.Util.AnalysisHighPrecisionBID[15],AFC56.Meters[15].Analysis.High_Precision.Stream*32+AFC56.Util.Meter_HighAnalysis+1+11264) ,XIO(AFC56.Meters[15].Analysis.High_Precision.EnableOnce) OTE(AFC56.Util.AnalysisHighPrecisionBID[15].8) ,MOV(AFC56.Util.AnalysisHighPrecisionBID[15],AFC56.outputbuffer[2]) ,COP(AFC56.Meters[15].Analysis.High_Precision.Components.C1,AFC56.outputbuffer[3],48) ];
   5: [MOV(AFC56.CycleCounter,AFC56.outputbuffer[0]) ,MOV(AFC56.outputbuffer[0],AFC56.outputbuffer[247]) ];
END_ROUTINE
